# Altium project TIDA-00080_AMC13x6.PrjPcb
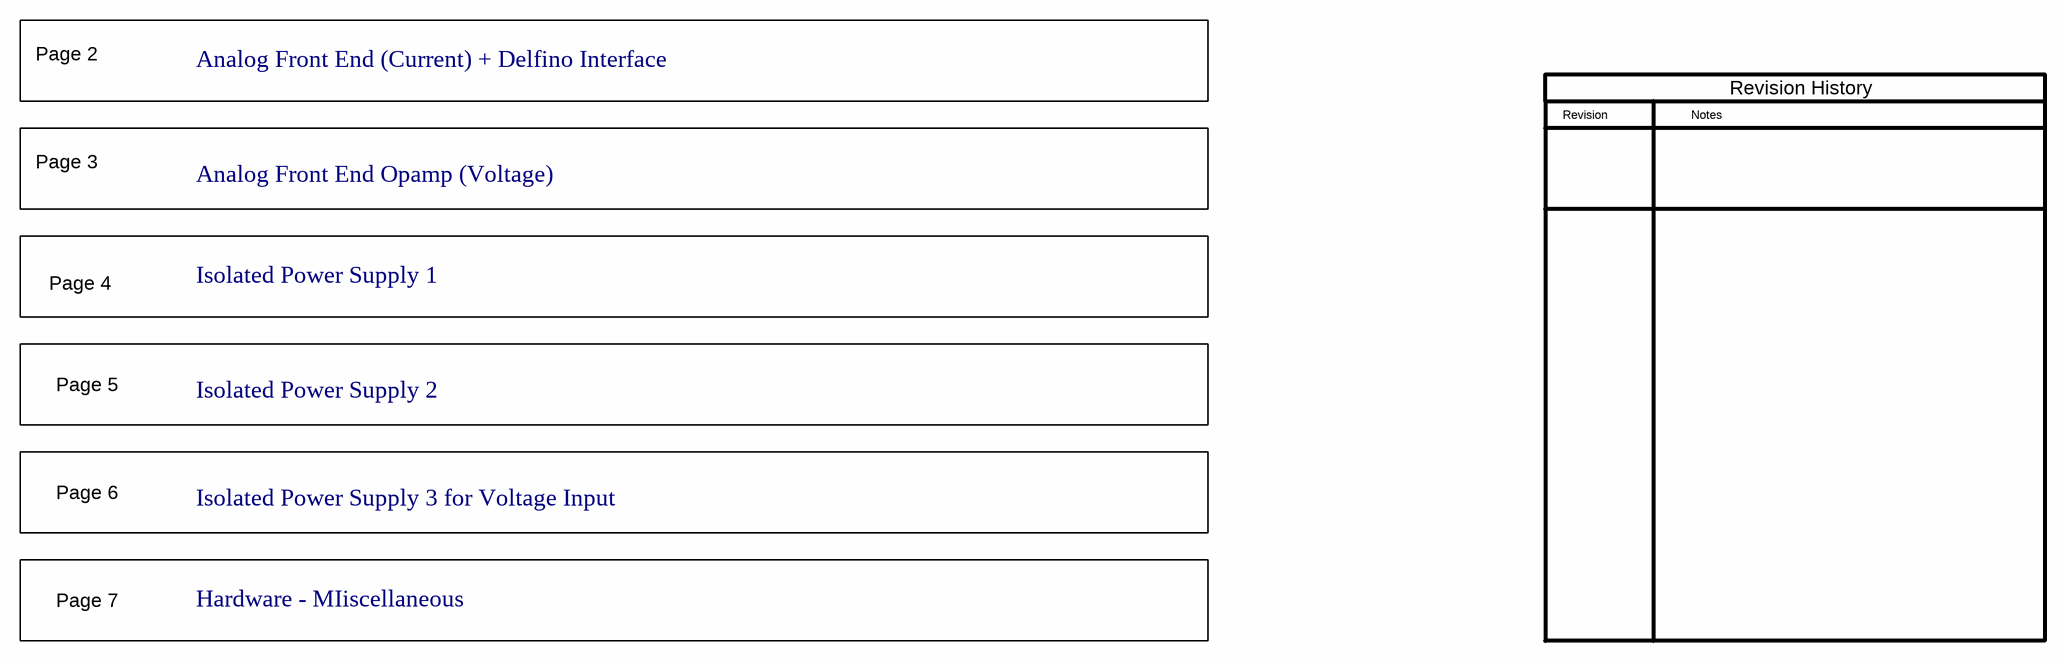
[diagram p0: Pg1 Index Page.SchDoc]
CopyrightYear: 2019; PCB_Layout: Avinash N; PCB_Rev: E1; PRJ_Customer: Public Release; PRJ_Engineer: Sreenivasa; PRJ_Number: TIDA-00080_AMC13x6; PRJ_Title: TIDA-00080_AMC13x6; SCH_Rev: E1; TechSupport: http://www.ti.com/support; TID: 00080
7 sheets, 373 parts. Net scope: flat (ports and power ports of the same name join across sheets).
Board file: TIDA-00080_AMC13x6.PcbDoc
Sheets:
  Pg1 Index Page.SchDoc
  Pg2-Current Sense.SchDoc
  Pg3-Voltage signal condtioning.SchDoc
  Pg4-Power supply 1.SchDoc
  Pg5-Power supply 2.SchDoc
  Pg6-Power supply 3.SchDoc
  Pg7-Hardware.SchDoc

## Sheet Pg1 Index Page.SchDoc: Index Page
size 431 x 279 mm; Date: Not shown in title block; ApprovedBy: Not shown in title block; CheckedBy: Not shown in title block; Author: Not shown in title block; CompanyName: Not shown in title block; Engineer: Not shown in title block; Organization: Not shown in title block; Address1: Not shown in title block; Address2: Not shown in title block; Address3: Not shown in title block; Address4: Not shown in title block; DocumentNumber: 1; Revision: Use project parameter SCH_Rev; SheetNumber: 1; SheetTotal: 7; PageSetup: Record=PageOptions¦CenterHorizontal=True¦CenterVertical=True¦PrintScale=1.00¦XCorrection=1.00¦YCorrection=1.00¦PrintKind=0¦BorderSize=5000000¦LeftOffset=0¦BottomOffset=0¦Orientation=2¦PaperLength=1000¦PaperWidth=1000¦Scale=100¦PaperSource=15¦PrintQuality=600¦MediaType=1¦DitherType=10¦PaperKind=Letter¦PrintScaleMode=1

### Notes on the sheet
- Page 2
- Analog Front End (Current) + Delfino Interface
- Revision
- Notes
- Revision History
- Page 3
- Analog Front End Opamp (Voltage)
- Page 4
- Isolated Power Supply 1
- Page 5
- Isolated Power Supply 2
- Page 6
- Isolated Power Supply 3 for Voltage Input
- Page 7
- Hardware - MIiscellaneous

## Sheet Pg2-Current Sense.SchDoc: Analog Front End (Current) + Delfino Interface
size 431 x 279 mm; Date: Not shown in title block; ApprovedBy: Not shown in title block; CheckedBy: Not shown in title block; Author: Not shown in title block; CompanyName: Not shown in title block; Engineer: Not shown in title block; Organization: Not shown in title block; Address1: Not shown in title block; Address2: Not shown in title block; Address3: Not shown in title block; Address4: Not shown in title block; DocumentNumber: 3; Revision: Use project parameter SCH_Rev; SheetNumber: 2; SheetTotal: 7; PageSetup: Record=PageOptions¦CenterHorizontal=True¦CenterVertical=True¦PrintScale=0.62¦XCorrection=1.00¦YCorrection=1.00¦PrintKind=0¦BorderSize=5000000¦LeftOffset=0¦BottomOffset=0¦Orientation=2¦PaperLength=1000¦PaperWidth=1000¦Scale=100¦PaperSource=15¦PrintQuality=600¦MediaType=1¦DitherType=10¦PaperKind=Letter¦PrintScaleMode=1
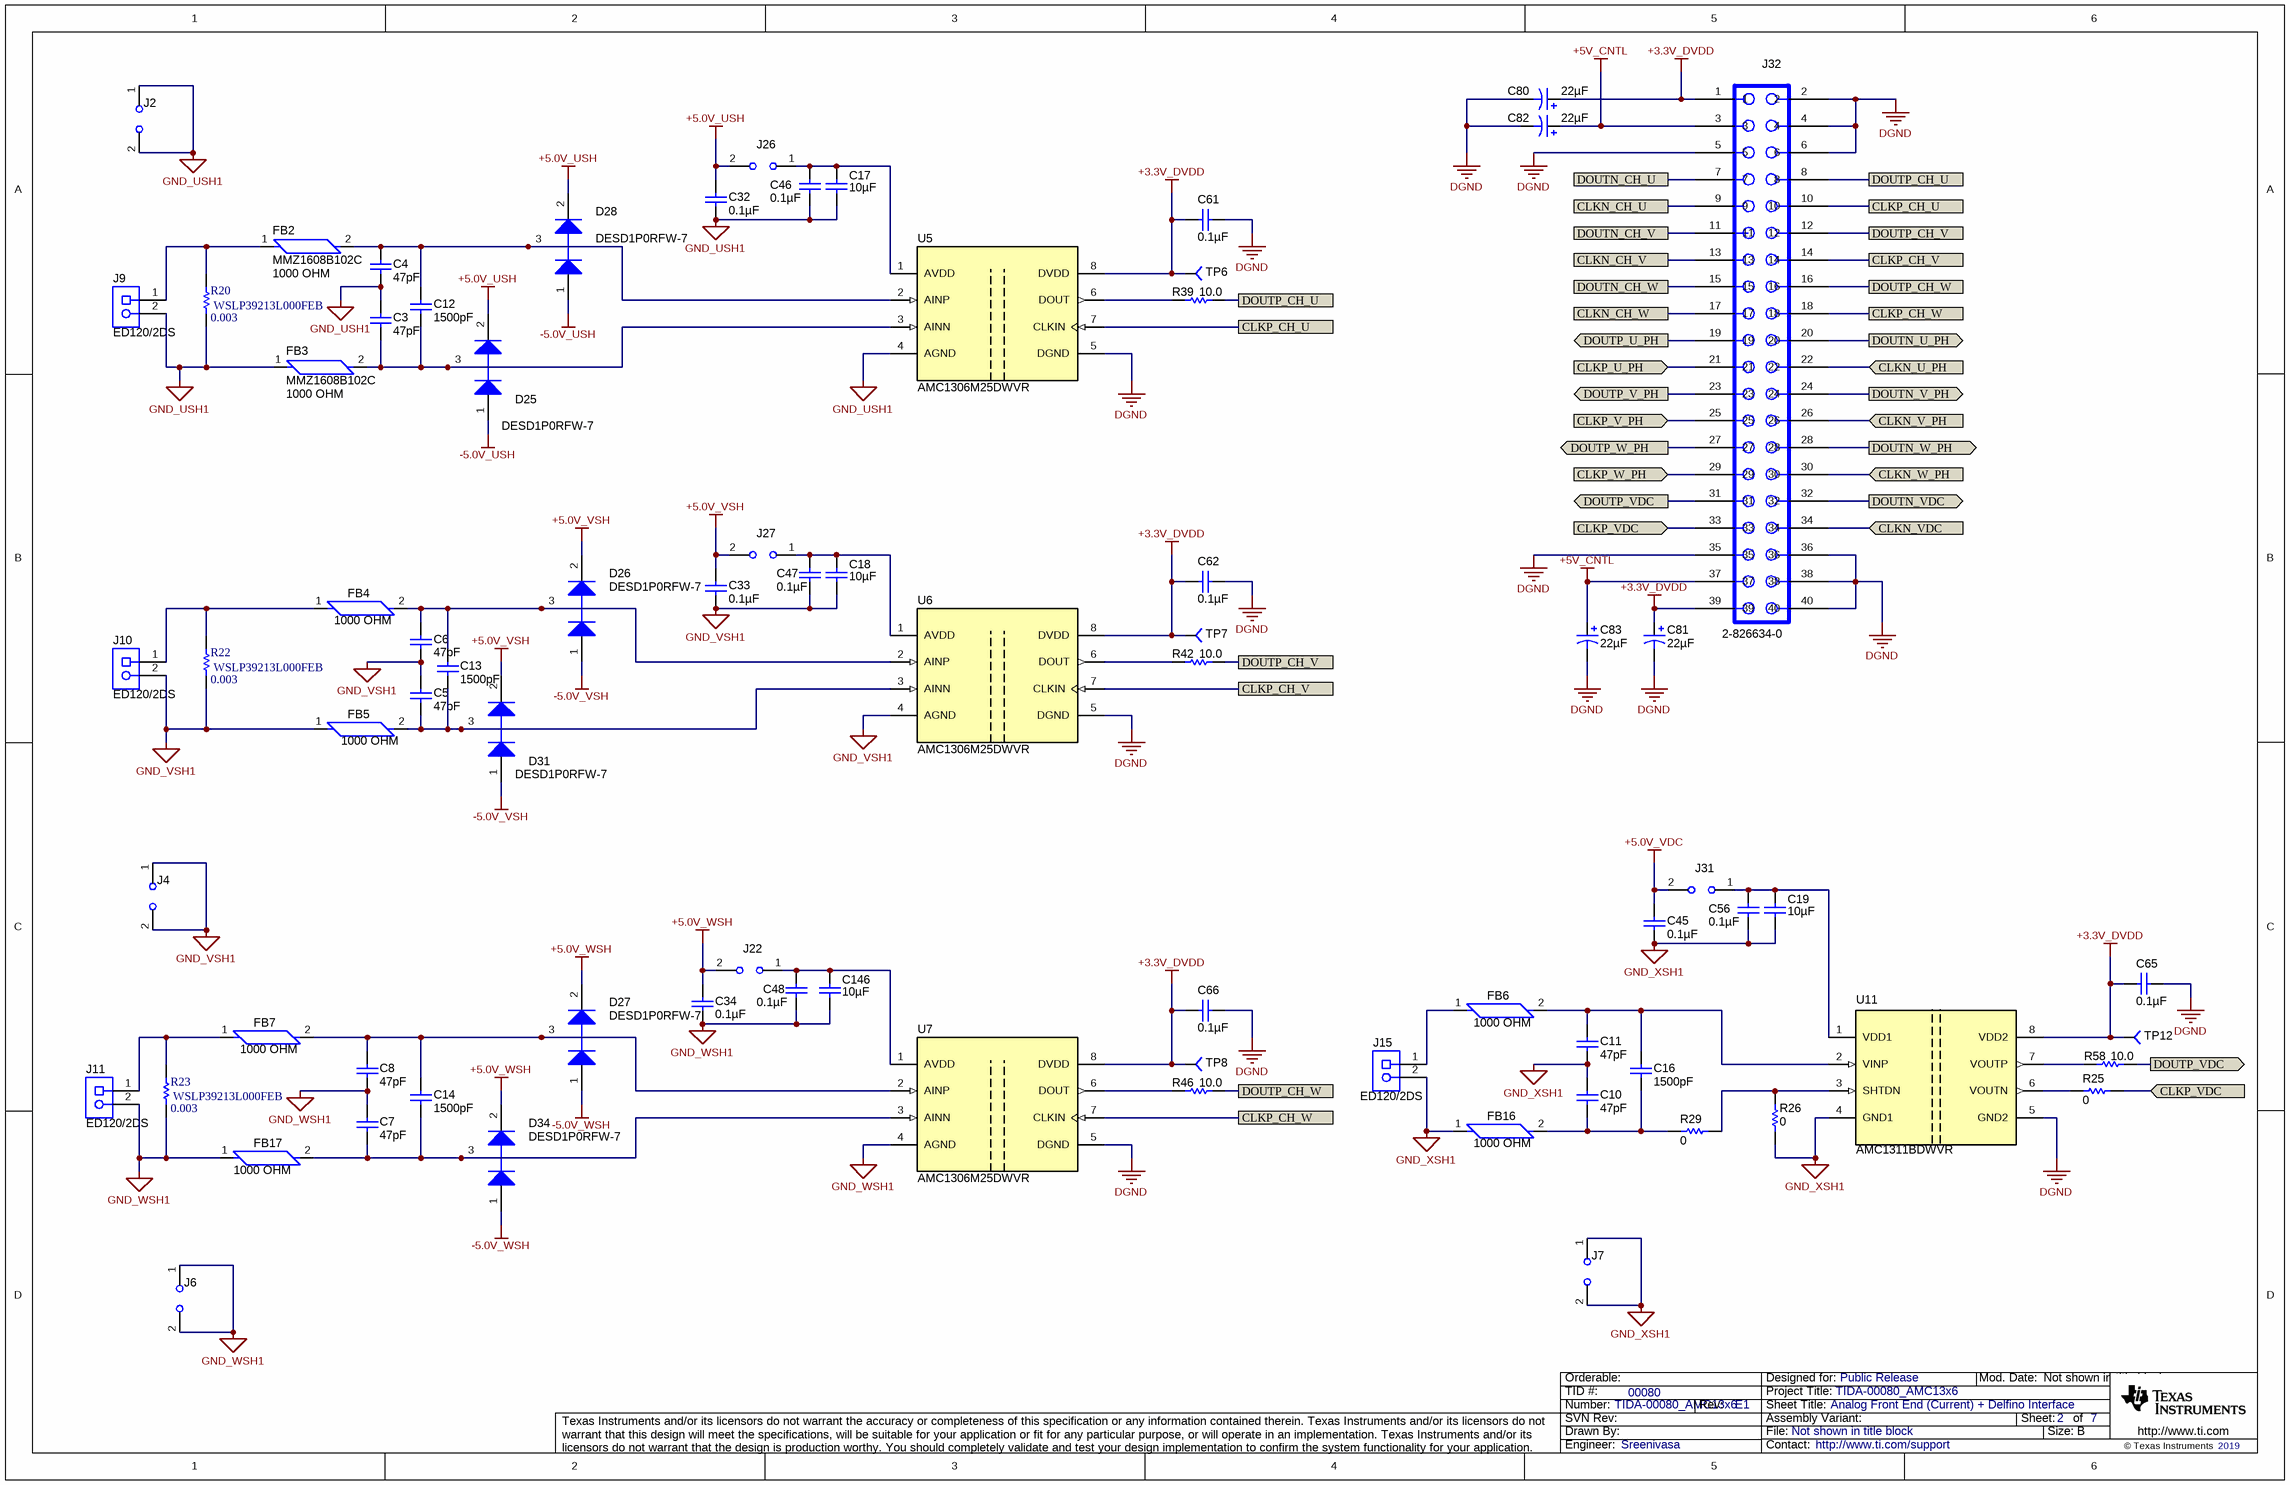
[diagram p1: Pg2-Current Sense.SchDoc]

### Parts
C3  ValueDisplayed: 47pF  [0805_HV]  (hidden comment: GRM21A5C2E470JW01D)
C4  ValueDisplayed: 47pF  [0805_HV]  (hidden comment: GRM21A5C2E470JW01D)
C5  ValueDisplayed: 47pF  [0805_HV]  (hidden comment: GRM21A5C2E470JW01D)
C6  ValueDisplayed: 47pF  [0805_HV]  (hidden comment: GRM21A5C2E470JW01D)
C7  ValueDisplayed: 47pF  [0805_HV]  (hidden comment: GRM21A5C2E470JW01D)
C8  ValueDisplayed: 47pF  [0805_HV]  (hidden comment: GRM21A5C2E470JW01D)
C10  ValueDisplayed: 47pF  [0805_HV]  (hidden comment: GRM21A5C2E470JW01D)
C11  ValueDisplayed: 47pF  [0805_HV]  (hidden comment: GRM21A5C2E470JW01D)
C12  ValueDisplayed: 1500pF  [0603]  (hidden comment: 06031C152KAT2A)
C13  ValueDisplayed: 1500pF  [0603]  (hidden comment: 06031C152KAT2A)
C14  ValueDisplayed: 1500pF  [0603]  (hidden comment: 06031C152KAT2A)
C16  ValueDisplayed: 1500pF  [0603]  (hidden comment: 06031C152KAT2A)
C17  ValueDisplayed: 10µF  [1210]
C18  ValueDisplayed: 10µF  [1210]
C19  ValueDisplayed: 10µF  [1210]
C32  ValueDisplayed: 0.1µF  [0603]
C33  ValueDisplayed: 0.1µF  [0603]
C34  ValueDisplayed: 0.1µF  [0603]
C45  ValueDisplayed: 0.1µF  [0603]
C46  ValueDisplayed: 0.1µF  [0603]
C47  ValueDisplayed: 0.1µF  [0603]
C48  ValueDisplayed: 0.1µF  [0603]
C56  ValueDisplayed: 0.1µF  [0603]
C61  ValueDisplayed: 0.1µF  [0603]
C62  ValueDisplayed: 0.1µF  [0603]
C65  ValueDisplayed: 0.1µF  [0603]
C66  ValueDisplayed: 0.1µF  [0603]
C80  ValueDisplayed: 22µF  [SM_RADIAL_5MM]  (hidden comment: UUD1E220MCL1GS)
C81  ValueDisplayed: 22µF  [SM_RADIAL_5MM]  (hidden comment: UUD1E220MCL1GS)
C82  ValueDisplayed: 22µF  [SM_RADIAL_5MM]  (hidden comment: UUD1E220MCL1GS)
C83  ValueDisplayed: 22µF  [SM_RADIAL_5MM]  (hidden comment: UUD1E220MCL1GS)
C146  ValueDisplayed: 10µF  [1210]
D25  value DESD1P0RFW-7  [SOT-323]
D26  DESD1P0RFW-7  [SOT-323]
D27  DESD1P0RFW-7  [SOT-323]
D28  value DESD1P0RFW-7  [SOT-323]
D31  DESD1P0RFW-7  [SOT-323]
D34  DESD1P0RFW-7  [SOT-323]
FB2  MMZ1608B102C  value 1000 OHM  [FB0603]
FB3  MMZ1608B102C  value 1000 OHM  [FB0603]
FB4  value 1000 OHM  [FB0603]  (hidden comment: MMZ1608B102C)
FB5  value 1000 OHM  [FB0603]  (hidden comment: MMZ1608B102C)
FB6  value 1000 OHM  [FB0603]  (hidden comment: MMZ1608B102C)
FB7  value 1000 OHM  [FB0603]  (hidden comment: MMZ1608B102C)
FB16  value 1000 OHM  [FB0603]  (hidden comment: MMZ1608B102C)
FB17  value 1000 OHM  [FB0603]  (hidden comment: MMZ1608B102C)
J2  (no value)  [HDR100_1X2]
J4  (no value)  [HDR100_1X2]
J6  (no value)  [HDR100_1X2]
J7  (no value)  [HDR100_1X2]
J9  ED120/2DS  [CONN_ED120-2DS]
J10  ED120/2DS  [CONN_ED120-2DS]
J11  ED120/2DS  [CONN_ED120-2DS]
J15  ED120/2DS  [CONN_ED120-2DS]
J22  (no value)  [HDR100_1X2]
J26  (no value)  [HDR100_1X2]
J27  (no value)  [HDR100_1X2]
J31  (no value)  [HDR100_1X2]
J32  2-826634-0  [CONN_61304021021]
R20  WSLP39213L000FEB  value 0.003  [RC3921]
R22  WSLP39213L000FEB  value 0.003  [RC3921]
R23  WSLP39213L000FEB  value 0.003  [RC3921]
R25  ValueDisplayed: 0  [0603]  (hidden comment: CRCW06030000Z0EA)
R26  ValueDisplayed: 0  [0603]  (hidden comment: CRCW06030000Z0EA)
R29  ValueDisplayed: 0  [0603]  (hidden comment: CRCW06030000Z0EA)
R39  value 10.0  [0603]
R42  value 10.0  [0603]
R46  value 10.0  [0603]
R58  value 10.0  [0603]
TP6  (no value)  [TP-040_RND]
TP7  (no value)  [TP-040_RND]
TP8  (no value)  [TP-040_RND]
TP12  (no value)  [TP-040_RND]
U5  AMC1306M25DWVR  [DWV0008A]
U6  AMC1306M25DWVR  [DWV0008A]
U7  AMC1306M25DWVR  [DWV0008A]
U11  AMC1311BDWVR  [DWV0008A]

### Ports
CLKN_CH_U, CLKN_CH_V, CLKN_CH_W, CLKN_U_PH (in), CLKN_V_PH (in), CLKN_VDC (in), CLKN_W_PH (in), CLKP_CH_U, CLKP_CH_V, CLKP_CH_W, CLKP_U_PH (in), CLKP_V_PH (in), CLKP_VDC (in), CLKP_W_PH (in), DOUTN_CH_U, DOUTN_CH_V, DOUTN_CH_W, DOUTN_U_PH (out), DOUTN_V_PH (out), DOUTN_VDC (out), DOUTN_W_PH (out), DOUTP_CH_U, DOUTP_CH_V, DOUTP_CH_W, DOUTP_U_PH (out), DOUTP_V_PH (out), DOUTP_VDC (out), DOUTP_W_PH (out)

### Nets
+3.3V_DVDD: C61.2 C62.2 C65.2 C66.2 C80.1(+) C81.1(+) J32.1 J32.39 TP6.1 TP7.1 TP8.1 TP12.1 U5.8(DVDD) U6.8(DVDD) U7.8(DVDD) U11.8(VDD2)
+5.0V_USH: C32.1 D25.2(K) D28.2(K) J26.2
+5.0V_VDC: C45.1 J31.2
+5.0V_VSH: C33.1 D26.2(K) D31.2(K) J27.2
+5.0V_WSH: C34.1 D27.2(K) D34.2(K) J22.2
+5V_CNTL: C82.1(+) C83.1(+) J32.3 J32.37
-5.0V_USH: D25.1(A) D28.1(A)
-5.0V_VSH: D26.1(A) D31.1(A)
-5.0V_WSH: D27.1(A) D34.1(A)
DGND: C61.1 C62.1 C65.1 C66.1 C80.2(-) C81.2(-) C82.2(-) C83.2(-) J32.2 J32.4 J32.5 J32.6 J32.35 J32.36 J32.38 J32.40 U5.5(DGND) U6.5(DGND) U7.5(DGND) U11.5(GND2)
GND_USH1: C3.1 C4.2 C17.1 C32.2 C46.2 FB3.1 J2.1 J2.2 J9.2 R20.1 U5.4(AGND)
GND_VSH1: C5.1 C6.2 C18.1 C33.2 C47.2 FB5.1 J4.1 J4.2 J10.2 R22.1 U6.4(AGND)
GND_WSH1: C7.1 C8.2 C34.2 C48.2 C146.1 FB17.1 J6.1 J6.2 J11.2 R23.1 U7.4(AGND)
GND_XSH1: C10.1 C11.2 C19.1 C45.2 C56.2 FB16.1 J7.1 J7.2 J15.2 R26.1 U11.4(GND1)
CLKN_CH_U: J32.9 ; port CLKN_CH_U
CLKN_CH_V: J32.13 ; port CLKN_CH_V
CLKN_CH_W: J32.17 ; port CLKN_CH_W
CLKN_U_PH: J32.22 ; port CLKN_U_PH
CLKN_V_PH: J32.26 ; port CLKN_V_PH
CLKN_VDC: J32.34 ; port CLKN_VDC
CLKN_W_PH: J32.30 ; port CLKN_W_PH
CLKP_CH_U: J32.10 U5.7(CLKIN) ; port CLKP_CH_U
CLKP_CH_V: J32.14 U6.7(CLKIN) ; port CLKP_CH_V
CLKP_CH_W: J32.18 U7.7(CLKIN) ; port CLKP_CH_W
CLKP_U_PH: J32.21 ; port CLKP_U_PH
CLKP_V_PH: J32.25 ; port CLKP_V_PH
CLKP_VDC: J32.33 R25.1 ; port CLKP_VDC
CLKP_W_PH: J32.29 ; port CLKP_W_PH
DOUTN_CH_U: J32.7 ; port DOUTN_CH_U
DOUTN_CH_V: J32.11 ; port DOUTN_CH_V
DOUTN_CH_W: J32.15 ; port DOUTN_CH_W
DOUTN_U_PH: J32.20 ; port DOUTN_U_PH
DOUTN_V_PH: J32.24 ; port DOUTN_V_PH
DOUTN_VDC: J32.32 ; port DOUTN_VDC
DOUTN_W_PH: J32.28 ; port DOUTN_W_PH
DOUTP_CH_U: J32.8 R39.2 ; port DOUTP_CH_U
DOUTP_CH_V: J32.12 R42.2 ; port DOUTP_CH_V
DOUTP_CH_W: J32.16 R46.2 ; port DOUTP_CH_W
DOUTP_U_PH: J32.19 ; port DOUTP_U_PH
DOUTP_V_PH: J32.23 ; port DOUTP_V_PH
DOUTP_VDC: J32.31 R58.2 ; port DOUTP_VDC
DOUTP_W_PH: J32.27 ; port DOUTP_W_PH
NetC3_2: C3.2 C12.2 D25.3(C) FB3.2 U5.3(AINN)
NetC4_1: C4.1 C12.1 D28.3(C) FB2.2 U5.2(AINP)
NetC5_2: C5.2 C13.2 D31.3(C) FB5.2 U6.3(AINN)
NetC6_1: C6.1 C13.1 D26.3(C) FB4.2 U6.2(AINP)
NetC7_2: C7.2 C14.2 D34.3(C) FB17.2 U7.3(AINN)
NetC8_1: C8.1 C14.1 D27.3(C) FB7.2 U7.2(AINP)
NetC10_2: C10.2 C16.2 FB16.2 R29.2
NetC11_1: C11.1 C16.1 FB6.2 U11.2(VINP)
NetC17_2: C17.2 C46.1 J26.1 U5.1(AVDD)
NetC18_2: C18.2 C47.1 J27.1 U6.1(AVDD)
NetC19_2: C19.2 C56.1 J31.1 U11.1(VDD1)
NetC48_1: C48.1 C146.2 J22.1 U7.1(AVDD)
NetFB2_1: FB2.1 J9.1 R20.2
NetFB4_1: FB4.1 J10.1 R22.2
NetFB6_1: FB6.1 J15.1
NetFB7_1: FB7.1 J11.1 R23.2
NetR25_2: R25.2 U11.6(VOUTN)
NetR26_2: R26.2 R29.1 U11.3(SHTDN)
NetR39_1: R39.1 U5.6(DOUT)
NetR42_1: R42.1 U6.6(DOUT)
NetR46_1: R46.1 U7.6(DOUT)
NetR58_1: R58.1 U11.7(VOUTP)

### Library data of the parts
C3-C8 C10 C11 = GRM21A5C2E470JW01D: CAP, CERM, 47pF, 500V, +/-5%, C0G/NP0, 0805; Manufacturer: MuRata; Polarized: N; CompType: Capacitor; U/M: EA; Cap_F: 0.000000000047; Tolerance_%: 5; Value1: Unknown; VDC_V: 250; Value2: 250V; TaMin_C: -55; TaMax_C: 125; Cap_Case: 0805
C12-C14 C16 = 06031C152KAT2A: CAP, CERM, 1500pF, 100V, +/-10%, X7R, 0603; Manufacturer: AVX; Polarized: N; CompType: Capacitor; U/M: EA; Cap_F: 0.0000000015; Tolerance_%: 10; ESR_Ohm: 0.229; Value1: 0.229 ohm; VDC_V: 100; TaMin_C: -55; TaMax_C: 125
C17-C19 C146 = GMK325AB7106MM-T: CAP, CERM, 10uF, 35V, +/-20%, X7R, 1210; Manufacturer: Taiyo Yuden; Polarized: N; CompType: Capacitor; U/M: EA; Cap_F: 0.00001; Tolerance_%: 20; Value1: Unknown; VDC_V: 35; TaMin_C: -55; TaMax_C: 125
C32-C34 C45-C48 C56 = C0603C104K5RACTU: CAP, CERM, 0.1uF, 50V, +/-10%, X7R, 0603; Manufacturer: Kemet; Polarized: N; CompType: Capacitor; U/M: EA; Cap_F: 0.0000001; Tolerance_%: 10; Value1: Unknown; VDC_V: 50; TaMin_C: -55; TaMax_C: 125
C61 C62 C65 C66 = 06033C104JAT2A: CAP, CERM, 0.1uF, 25V, +/-5%, X7R, 0603; Manufacturer: AVX; Polarized: N; CompType: Capacitor; U/M: EA; Cap_F: 0.0000001; Tolerance_%: 5; ESR_Ohm: 0.05; Value1: 0.05 ohm; VDC_V: 25; TaMin_C: -55; TaMax_C: 125
C80-C83 = UUD1E220MCL1GS: CAP, AL, 22uF, 25V, +/-20%, 0.76 ohm, SMD; Manufacturer: Nichicon; Polarized: Y; CompType: Capacitor; U/M: EA; Cap_F: 0.000022; Tolerance_%: 20; VDC_V: 25; ESR_Ohm: 0.76; IRMS_A: 0.15; TaMin_C: -55; TaMax_C: 105; Cap_Case: 5x5.8
D25 D28 = BAV99WT1G: Diode, P-N, 70V, 0.2A, SOT-323; Manufacturer: Diodes Inc
D26 D27 D31 D34 = BAV99WT1G: Diode, P-N, 70V, 0.2A, SOT-323; Manufacturer: Diodes Inc; Value: DNP
FB2-FB7 FB16 FB17 = MMZ1608B102C: FERRITE CHIP 1000 OHM 300MA 0603; Manufacturer: TDK Corporation; CompType: Ferrite Bead
J2 J4 J6 J7 J22 J26 J27 J31 = JUMPER_2X100MIL: Header, Male 2-pin, 100mil spacing,; Manufacturer: FCI; PartNumber: 68001-402HLF; area: 20000; Value: 68001-402HLF
J9-J11 J15 = ED120/2DS: TERMINAL BLOCK 5.08MM VERT 2POS, TH; Manufacturer: On-Shore Technology; SymbolCreator: a0412235; U/M: EA
J32 = CONN_61304021021: Connector, Right Angle 2x20 pin, 100mil spacing; Manufacturer: TE Connectivity; area: 1.262.250
R20 R22 R23 = WSLP39213L000FEB: RESISTOR, SMD, 0.003 OHM, 1%, 5W, 3921; Manufacturer: VISHAY DALE; SymbolCreator: x0199378
R25 R26 R29 = CRCW06030000Z0EA: RES, 0, 5%, 0.1 W, 0603; Manufacturer: Vishay-Dale; CompType: Resistor; Value: 0; Value_Code: 0000; Tolerance_%: 5; Power_W: 0.1; Value2: 0.1W; VDC_V: 75; TempCo: 200 ppm/C; SizeArea_mm2: 1.28; SizeX_mm: 1.6; SizeY_mm: 0.8; SizeZ_mm: 1; EIA_Code: E24; U/M: EA; AEC Category: Q200; Green_Lifecycle: Active; Green_REACh: Passed
R39 R42 R46 R58 = CRCW060310R0FKEA: RES, 10.0 ohm, 1%, 0.1W, 0603; Manufacturer: Vishay-Dale; CompType: Resistor; Res_ohm: 10; Value_Code: 10R0; Tolerance_%: 1; Power_W: 0.1; VDC_V: 75; TempCo: 100 ppm/C; EIA_Code: E96; U/M: EA
TP6-TP8 TP12 = TP-040_RND: Test Point, O.040 Hole; Manufacturer: STD; Value: STD
U5-U7 = AMC1306M25DWVR: Small Reinforced Isolated Modulator With +/-250mV Input and CMOS Interface, DWV0008A (SOIC-8); Manufacturer: Texas Instruments; SymbolCreator: Altium; SizeArea_mm2: 67.275; SizeAreaWB_mm2: 105.975; SizeX_mm: 11.5; SizeY_mm: 5.85; SizeZ_mm: 2.8; CompType: IC; U/M: EA
U11 = AMC1311DWVR: Precision, 2-V Input, Reinforced Isolated Amplifier, DWV0008A (SOIC-8); Manufacturer: Texas Instruments; SymbolCreator: a0411947; SizeArea_mm2: 67.275; SizeAreaWB_mm2: 105.975; SizeX_mm: 11.5; SizeY_mm: 5.85; SizeZ_mm: 2.8; CompType: IC; U/M: EA

## Sheet Pg3-Voltage signal condtioning.SchDoc: Analog Front End Opamp (Voltage)
size 431 x 279 mm; Date: Not shown in title block; ApprovedBy: Not shown in title block; CheckedBy: Not shown in title block; Author: Not shown in title block; CompanyName: Not shown in title block; Engineer: Not shown in title block; Organization: Not shown in title block; Address1: Not shown in title block; Address2: Not shown in title block; Address3: Not shown in title block; Address4: Not shown in title block; DocumentNumber: 4; Revision: Use project parameter SCH_Rev; SheetNumber: 3; SheetTotal: 7; PageSetup: Record=PageOptions¦CenterHorizontal=True¦CenterVertical=True¦PrintScale=1.00¦XCorrection=1.00¦YCorrection=1.00¦PrintKind=0¦BorderSize=5000000¦LeftOffset=0¦BottomOffset=0¦Orientation=2¦PaperLength=1000¦PaperWidth=1000¦Scale=100¦PaperSource=15¦PrintQuality=600¦MediaType=1¦DitherType=10¦PaperKind=Letter¦PrintScaleMode=1
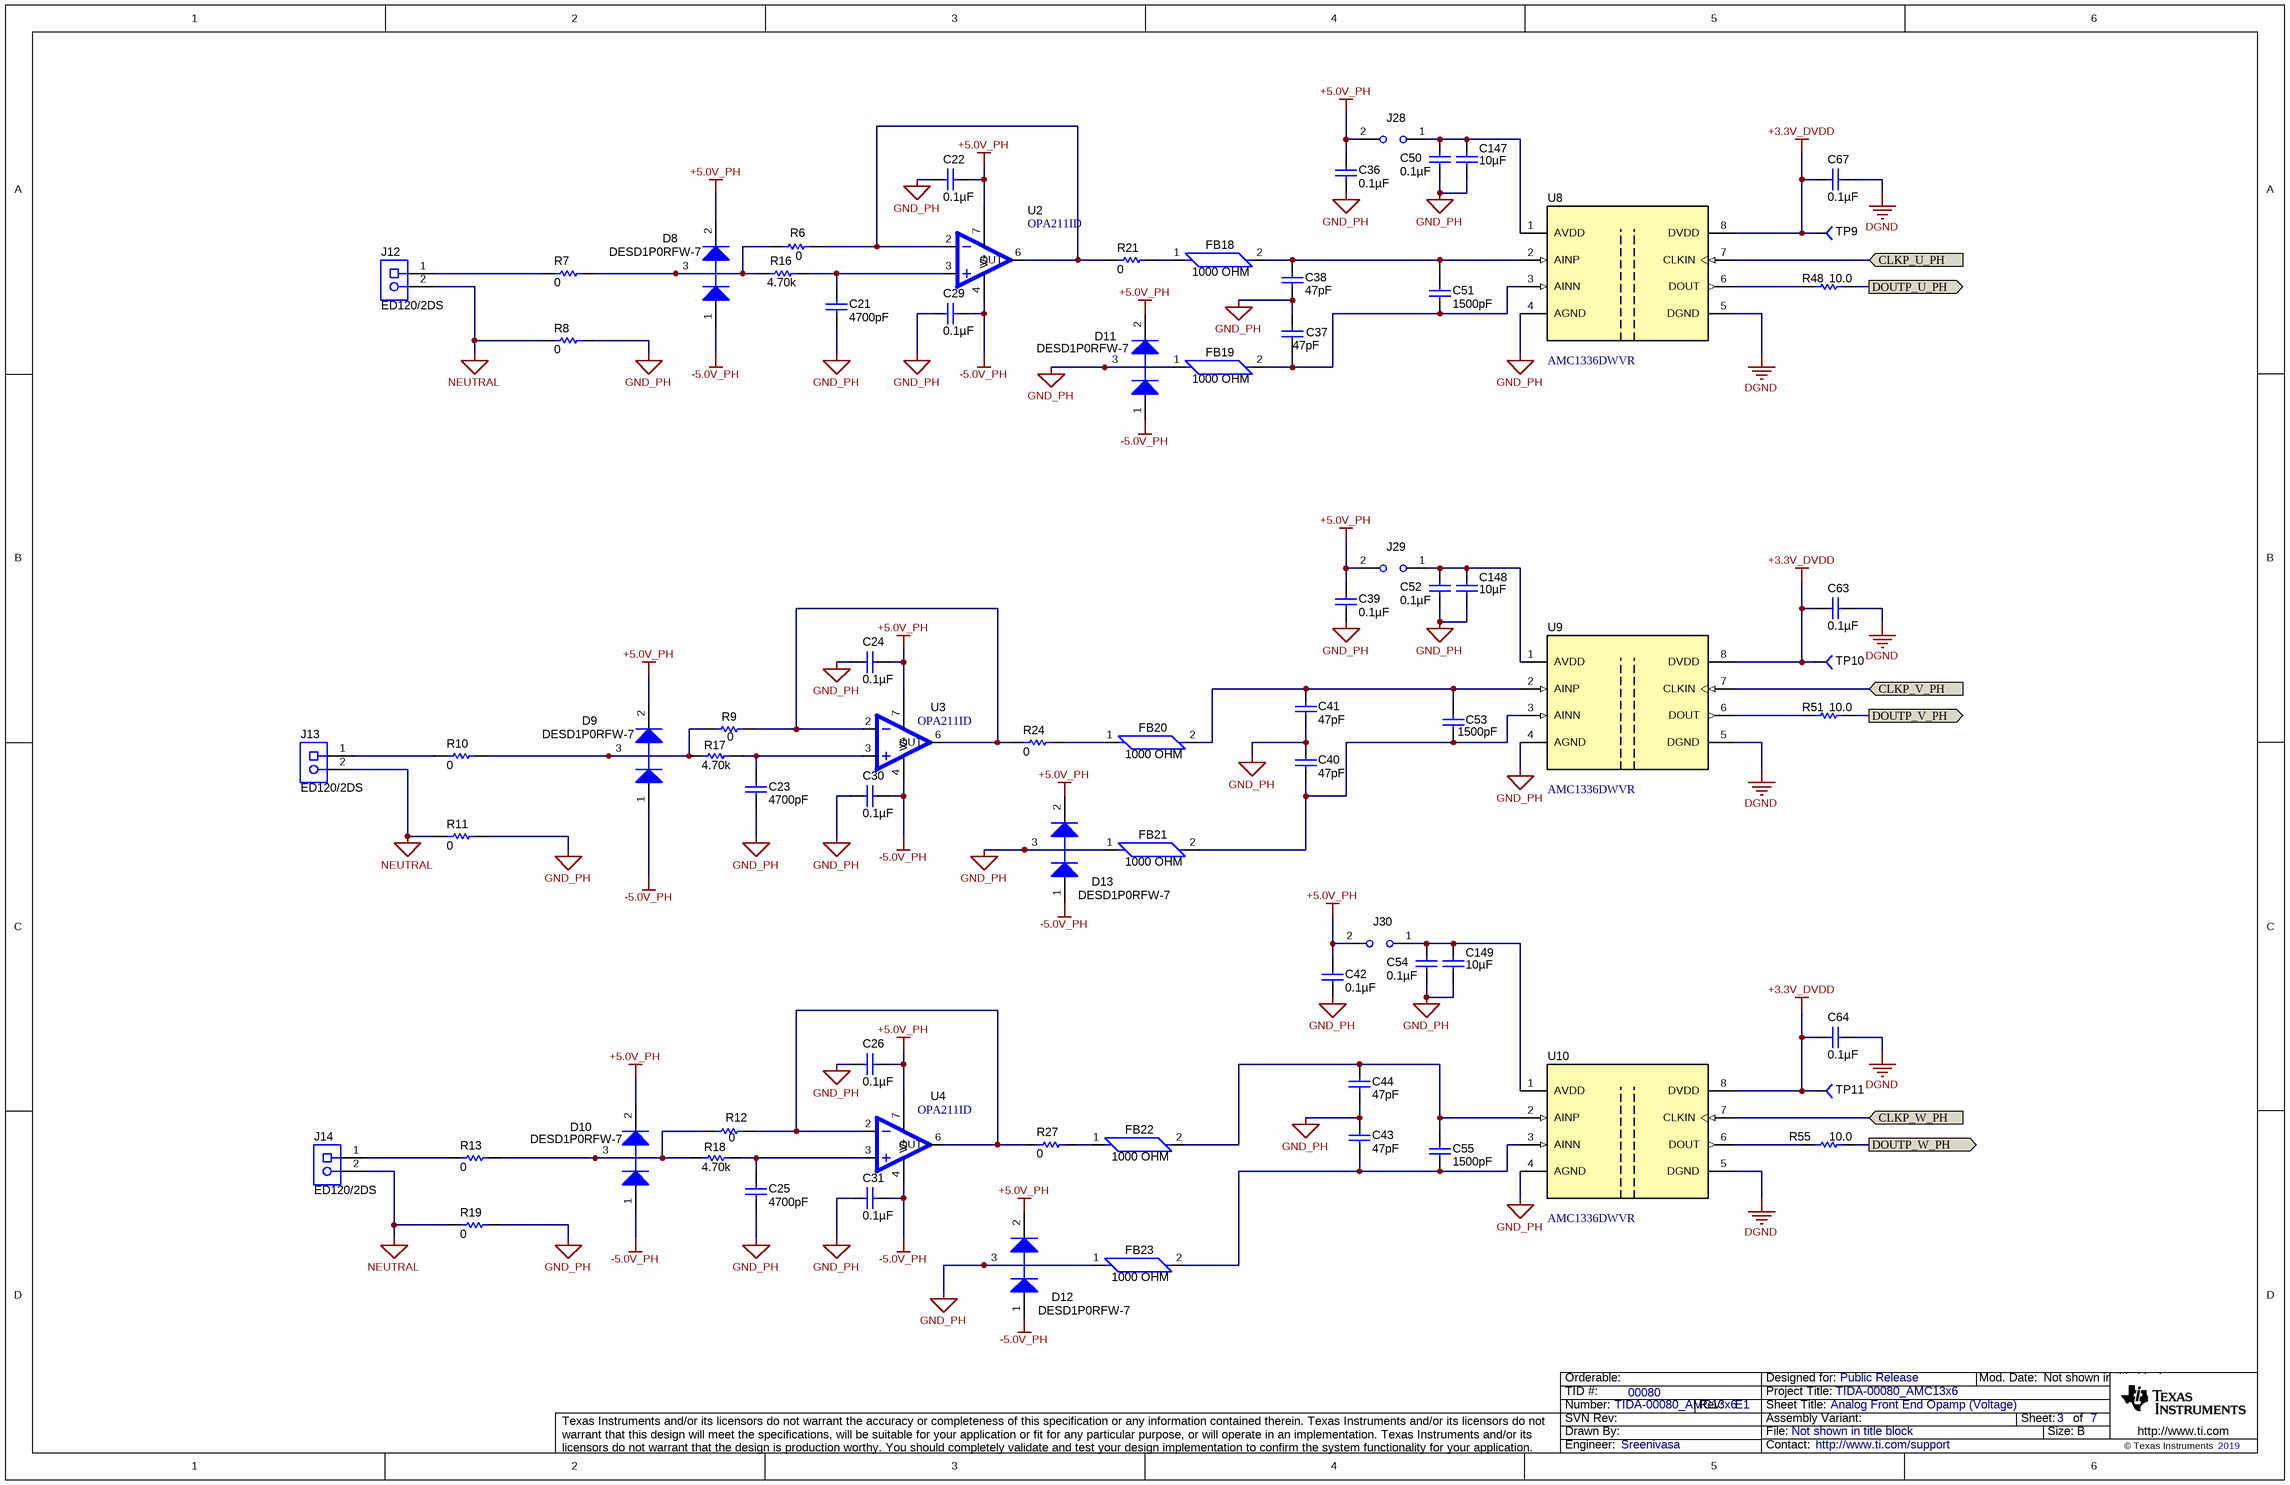
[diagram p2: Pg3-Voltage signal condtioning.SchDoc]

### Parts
C21  ValueDisplayed: 4700pF  [0603]
C22  ValueDisplayed: 0.1µF  [0603]
C23  ValueDisplayed: 4700pF  [0603]
C24  ValueDisplayed: 0.1µF  [0603]
C25  ValueDisplayed: 4700pF  [0603]
C26  ValueDisplayed: 0.1µF  [0603]
C29  ValueDisplayed: 0.1µF  [0603]
C30  ValueDisplayed: 0.1µF  [0603]
C31  ValueDisplayed: 0.1µF  [0603]
C36  ValueDisplayed: 0.1µF  [0603]
C37  ValueDisplayed: 47pF  [0805_HV]  (hidden comment: GRM21A5C2E470JW01D)
C38  ValueDisplayed: 47pF  [0805_HV]  (hidden comment: GRM21A5C2E470JW01D)
C39  ValueDisplayed: 0.1µF  [0603]
C40  ValueDisplayed: 47pF  [0805_HV]  (hidden comment: GRM21A5C2E470JW01D)
C41  ValueDisplayed: 47pF  [0805_HV]  (hidden comment: GRM21A5C2E470JW01D)
C42  ValueDisplayed: 0.1µF  [0603]
C43  ValueDisplayed: 47pF  [0805_HV]  (hidden comment: GRM21A5C2E470JW01D)
C44  ValueDisplayed: 47pF  [0805_HV]  (hidden comment: GRM21A5C2E470JW01D)
C50  ValueDisplayed: 0.1µF  [0603]
C51  ValueDisplayed: 1500pF  [0603]  (hidden comment: 06031C152KAT2A)
C52  ValueDisplayed: 0.1µF  [0603]
C53  ValueDisplayed: 1500pF  [0603]  (hidden comment: 06031C152KAT2A)
C54  ValueDisplayed: 0.1µF  [0603]
C55  ValueDisplayed: 1500pF  [0603]  (hidden comment: 06031C152KAT2A)
C63  ValueDisplayed: 0.1µF  [0603]
C64  ValueDisplayed: 0.1µF  [0603]
C67  ValueDisplayed: 0.1µF  [0603]
C147  ValueDisplayed: 10µF  [1210]
C148  ValueDisplayed: 10µF  [1210]
C149  ValueDisplayed: 10µF  [1210]
D8  DESD1P0RFW-7  [SOT-323]
D9  DESD1P0RFW-7  [SOT-323]
D10  DESD1P0RFW-7  [SOT-323]
D11  value DESD1P0RFW-7  [SOT-323]
D12  value DESD1P0RFW-7  [SOT-323]
D13  value DESD1P0RFW-7  [SOT-323]
FB18  value 1000 OHM  [FB0603]  (hidden comment: MMZ1608B102C)
FB19  value 1000 OHM  [FB0603]  (hidden comment: MMZ1608B102C)
FB20  value 1000 OHM  [FB0603]  (hidden comment: MMZ1608B102C)
FB21  value 1000 OHM  [FB0603]  (hidden comment: MMZ1608B102C)
FB22  value 1000 OHM  [FB0603]  (hidden comment: MMZ1608B102C)
FB23  value 1000 OHM  [FB0603]  (hidden comment: MMZ1608B102C)
J12  ED120/2DS  [CONN_ED120-2DS]
J13  ED120/2DS  [CONN_ED120-2DS]
J14  ED120/2DS  [CONN_ED120-2DS]
J28  (no value)  [HDR100_1X2]
J29  (no value)  [HDR100_1X2]
J30  (no value)  [HDR100_1X2]
R6  value 0  [0603]  (hidden comment: CRCW06030000Z0EA)
R7  value 0  [0805_HV]  (hidden comment: CRCW08050000Z0EA)
R8  value 0  [0805_HV]  (hidden comment: CRCW08050000Z0EA)
R9  value 0  [0603]  (hidden comment: CRCW06030000Z0EA)
R10  value 0  [0805_HV]  (hidden comment: CRCW08050000Z0EA)
R11  value 0  [0805_HV]  (hidden comment: CRCW08050000Z0EA)
R12  value 0  [0603]  (hidden comment: CRCW06030000Z0EA)
R13  value 0  [0805_HV]  (hidden comment: CRCW08050000Z0EA)
R16  value 4.70k  [0603]
R17  value 4.70k  [0603]
R18  value 4.70k  [0603]
R19  value 0  [0805_HV]  (hidden comment: CRCW08050000Z0EA)
R21  value 0  [0603]
R24  value 0  [0603]
R27  value 0  [0603]
R48  value 10.0  [0603]
R51  value 10.0  [0603]
R55  value 10.0  [0603]
TP9  (no value)  [TP-040_RND]
TP10  (no value)  [TP-040_RND]
TP11  (no value)  [TP-040_RND]
U2  OPA211ID  [SO8]
U3  OPA211ID  [SO8]
U4  OPA211ID  [SO8]
U8  AMC1336DWVR  [DWV0008A]
U9  AMC1336DWVR  [DWV0008A]
U10  AMC1336DWVR  [DWV0008A]

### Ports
CLKP_U_PH (in), CLKP_V_PH (in), CLKP_W_PH (in), DOUTP_U_PH (out), DOUTP_V_PH (out), DOUTP_W_PH (out)

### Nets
+3.3V_DVDD: C63.2 C64.2 C67.2 TP9.1 TP10.1 TP11.1 U8.8(DVDD) U9.8(DVDD) U10.8(DVDD)
+5.0V_PH: C22.2 C24.2 C26.2 C36.1 C39.1 C42.1 D8.2(K) D9.2(K) D10.2(K) D11.2(K) D12.2(K) D13.2(K) J28.2 J29.2 J30.2 U2.7(V+) U3.7(V+) U4.7(V+)
-5.0V_PH: C29.2 C30.2 C31.2 D8.1(A) D9.1(A) D10.1(A) D11.1(A) D12.1(A) D13.1(A) U2.4(V-) U3.4(V-) U4.4(V-)
DGND: C63.1 C64.1 C67.1 U8.5(DGND) U9.5(DGND) U10.5(DGND)
GND_PH: C21.2 C22.1 C23.2 C24.1 C25.2 C26.1 C29.1 C30.1 C31.1 C36.2 C37.1 C38.1 C39.2 C40.1 C41.1 C42.2 C43.1 C44.1 C50.2 C52.2 C54.2 C147.1 C148.1 C149.1 D11.3(C) D12.3(C) D13.3(C) FB19.1 FB21.1 FB23.1 R8.2 R11.2 R19.2 U8.4(AGND) U9.4(AGND) U10.4(AGND)
NEUTRAL: J12.2 J13.2 J14.2 R8.1 R11.1 R19.1
CLKP_U_PH: U8.7(CLKIN) ; port CLKP_U_PH
CLKP_V_PH: U9.7(CLKIN) ; port CLKP_V_PH
CLKP_W_PH: U10.7(CLKIN) ; port CLKP_W_PH
DOUTP_U_PH: R48.2 ; port DOUTP_U_PH
DOUTP_V_PH: R51.2 ; port DOUTP_V_PH
DOUTP_W_PH: R55.2 ; port DOUTP_W_PH
NetC21_1: C21.1 R16.2 U2.3
NetC23_1: C23.1 R17.2 U3.3
NetC25_1: C25.1 R18.2 U4.3
NetC37_2: C37.2 C51.2 FB19.2 U8.3(AINN)
NetC38_2: C38.2 C51.1 FB18.2 U8.2(AINP)
NetC40_2: C40.2 C53.2 FB21.2 U9.3(AINN)
NetC41_2: C41.2 C53.1 FB20.2 U9.2(AINP)
NetC43_2: C43.2 C55.2 FB23.2 U10.3(AINN)
NetC44_2: C44.2 C55.1 FB22.2 U10.2(AINP)
NetC50_1: C50.1 C147.2 J28.1 U8.1(AVDD)
NetC52_1: C52.1 C148.2 J29.1 U9.1(AVDD)
NetC54_1: C54.1 C149.2 J30.1 U10.1(AVDD)
NetD8_3: D8.3(C) R6.1 R7.2 R16.1
NetD9_3: D9.3(C) R9.1 R10.2 R17.1
NetD10_3: D10.3(C) R12.1 R13.2 R18.1
NetFB18_1: FB18.1 R21.2
NetFB20_1: FB20.1 R24.2
NetFB22_1: FB22.1 R27.2
NetJ12_1: J12.1 R7.1
NetJ13_1: J13.1 R10.1
NetJ14_1: J14.1 R13.1
NetR6_2: R6.2 R21.1 U2.2 U2.6(OUT)
NetR9_2: R9.2 R24.1 U3.2 U3.6(OUT)
NetR12_2: R12.2 R27.1 U4.2 U4.6(OUT)
NetR48_1: R48.1 U8.6(DOUT)
NetR51_1: R51.1 U9.6(DOUT)
NetR55_1: R55.1 U10.6(DOUT)

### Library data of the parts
C21 C23 C25 = 06031C472KAT2A: CAP, CERM, 4700pF, 100V, +/-10%, X7R, 0603; Manufacturer: AVX; Polarized: N; CompType: Capacitor; U/M: EA; Cap_F: 0.0000000047; Tolerance_%: 10; ESR_Ohm: 0.136; Value1: 0.136 ohm; VDC_V: 100; TaMin_C: -55; TaMax_C: 125
C22 C24 C26 C29-C31 C36 C39 C42 C50 C52 C54 = C0603C104K5RACTU: as C32 on sheet Pg2-Current Sense
C37 C38 C40 C41 C43 C44 = GRM21A5C2E470JW01D: as C3 on sheet Pg2-Current Sense
C51 C53 C55 = 06031C152KAT2A: as C12 on sheet Pg2-Current Sense
C63 C64 C67 = 06033C104JAT2A: as C61 on sheet Pg2-Current Sense
C147-C149 = GMK325AB7106MM-T: as C17 on sheet Pg2-Current Sense
D8-D10 = BAV99WT1G: as D26 on sheet Pg2-Current Sense
D11-D13 = BAV99WT1G: as D25 on sheet Pg2-Current Sense
FB18-FB23 = MMZ1608B102C: as FB2 on sheet Pg2-Current Sense
J12-J14 = ED120/2DS: as J9 on sheet Pg2-Current Sense
J28-J30 = JUMPER_2X100MIL: as J2 on sheet Pg2-Current Sense
R6 R9 R12 R21 R24 R27 = CRCW06030000Z0EA: RES, 0 ohm, 5%, 0.1W, 0603; Manufacturer: Vishay-Dale; CompType: Resistor; Value_Code: 0000; Tolerance_%: 5; Power_W: 0.1; VDC_V: 75; TempCo: 200 ppm/C; EIA_Code: E24; U/M: EA
R7 R8 R10 R11 R13 R19 = CRCW08050000Z0EA: RES, 0 ohm, 5%, 0.125W, 0805; Manufacturer: Vishay-Dale; CompType: Resistor; Value_Code: 0000; Tolerance_%: 5; Power_W: 0.125; VDC_V: 150; TempCo: 200 ppm/C; EIA_Code: E24; U/M: EA
R16-R18 = RC0603FR-074K7L: RES, 4.70k ohm, 1%, 0.1W, 0603; Manufacturer: Yageo America; CompType: Resistor; Res_ohm: 4700; Value_Code: 4k70; Tolerance_%: 1; Power_W: 0.1; VDC_V: 150; TempCo: 200 ppm/C; U/M: EA
R48 R51 R55 = CRCW060310R0FKEA: as R39 on sheet Pg2-Current Sense
TP9-TP11 = TP-040_RND: as TP6 on sheet Pg2-Current Sense
U2-U4 = OPA211AID: IC, 1.1nV/vHz Noise, Low Power, Precision OpAmp; Manufacturer: Texas Instruments; Alternate Manufacturer: None; Area: 75900
U8-U10 = CMP-0860008-1: AMC1336 Small, High-Precision, Reinforced Isolated Delta-Sigma Modulator With Input Optimized for Voltage Sensing Applications, DWV0008A (SOIC-8); Manufacturer: Texas Instruments; AEC Qualified: N; AEC Category: Q200; SizeY_mm: 5.85; SizeX_mm: 11.5; SizeAreaWB_mm2: 105.975; SizeArea_mm2: 67.275; CompType: IC; SizeZ_mm: 2.8

## Sheet Pg4-Power supply 1.SchDoc: Isolated Poser Supply 1
size 431 x 279 mm; Date: Not shown in title block; ApprovedBy: Not shown in title block; CheckedBy: Not shown in title block; Author: Not shown in title block; CompanyName: Not shown in title block; Engineer: Not shown in title block; Organization: Not shown in title block; Address1: Not shown in title block; Address2: Not shown in title block; Address3: Not shown in title block; Address4: Not shown in title block; DocumentNumber: 5; Revision: Use project parameter SCH_Rev; SheetNumber: 4; SheetTotal: 7; PageSetup: Record=PageOptions¦CenterHorizontal=True¦CenterVertical=True¦PrintScale=0.62¦XCorrection=1.00¦YCorrection=1.00¦PrintKind=0¦BorderSize=5000000¦LeftOffset=0¦BottomOffset=0¦Orientation=2¦PaperLength=1000¦PaperWidth=1000¦Scale=100¦PaperSource=15¦PrintQuality=600¦MediaType=1¦DitherType=10¦PaperKind=Letter¦PrintScaleMode=1
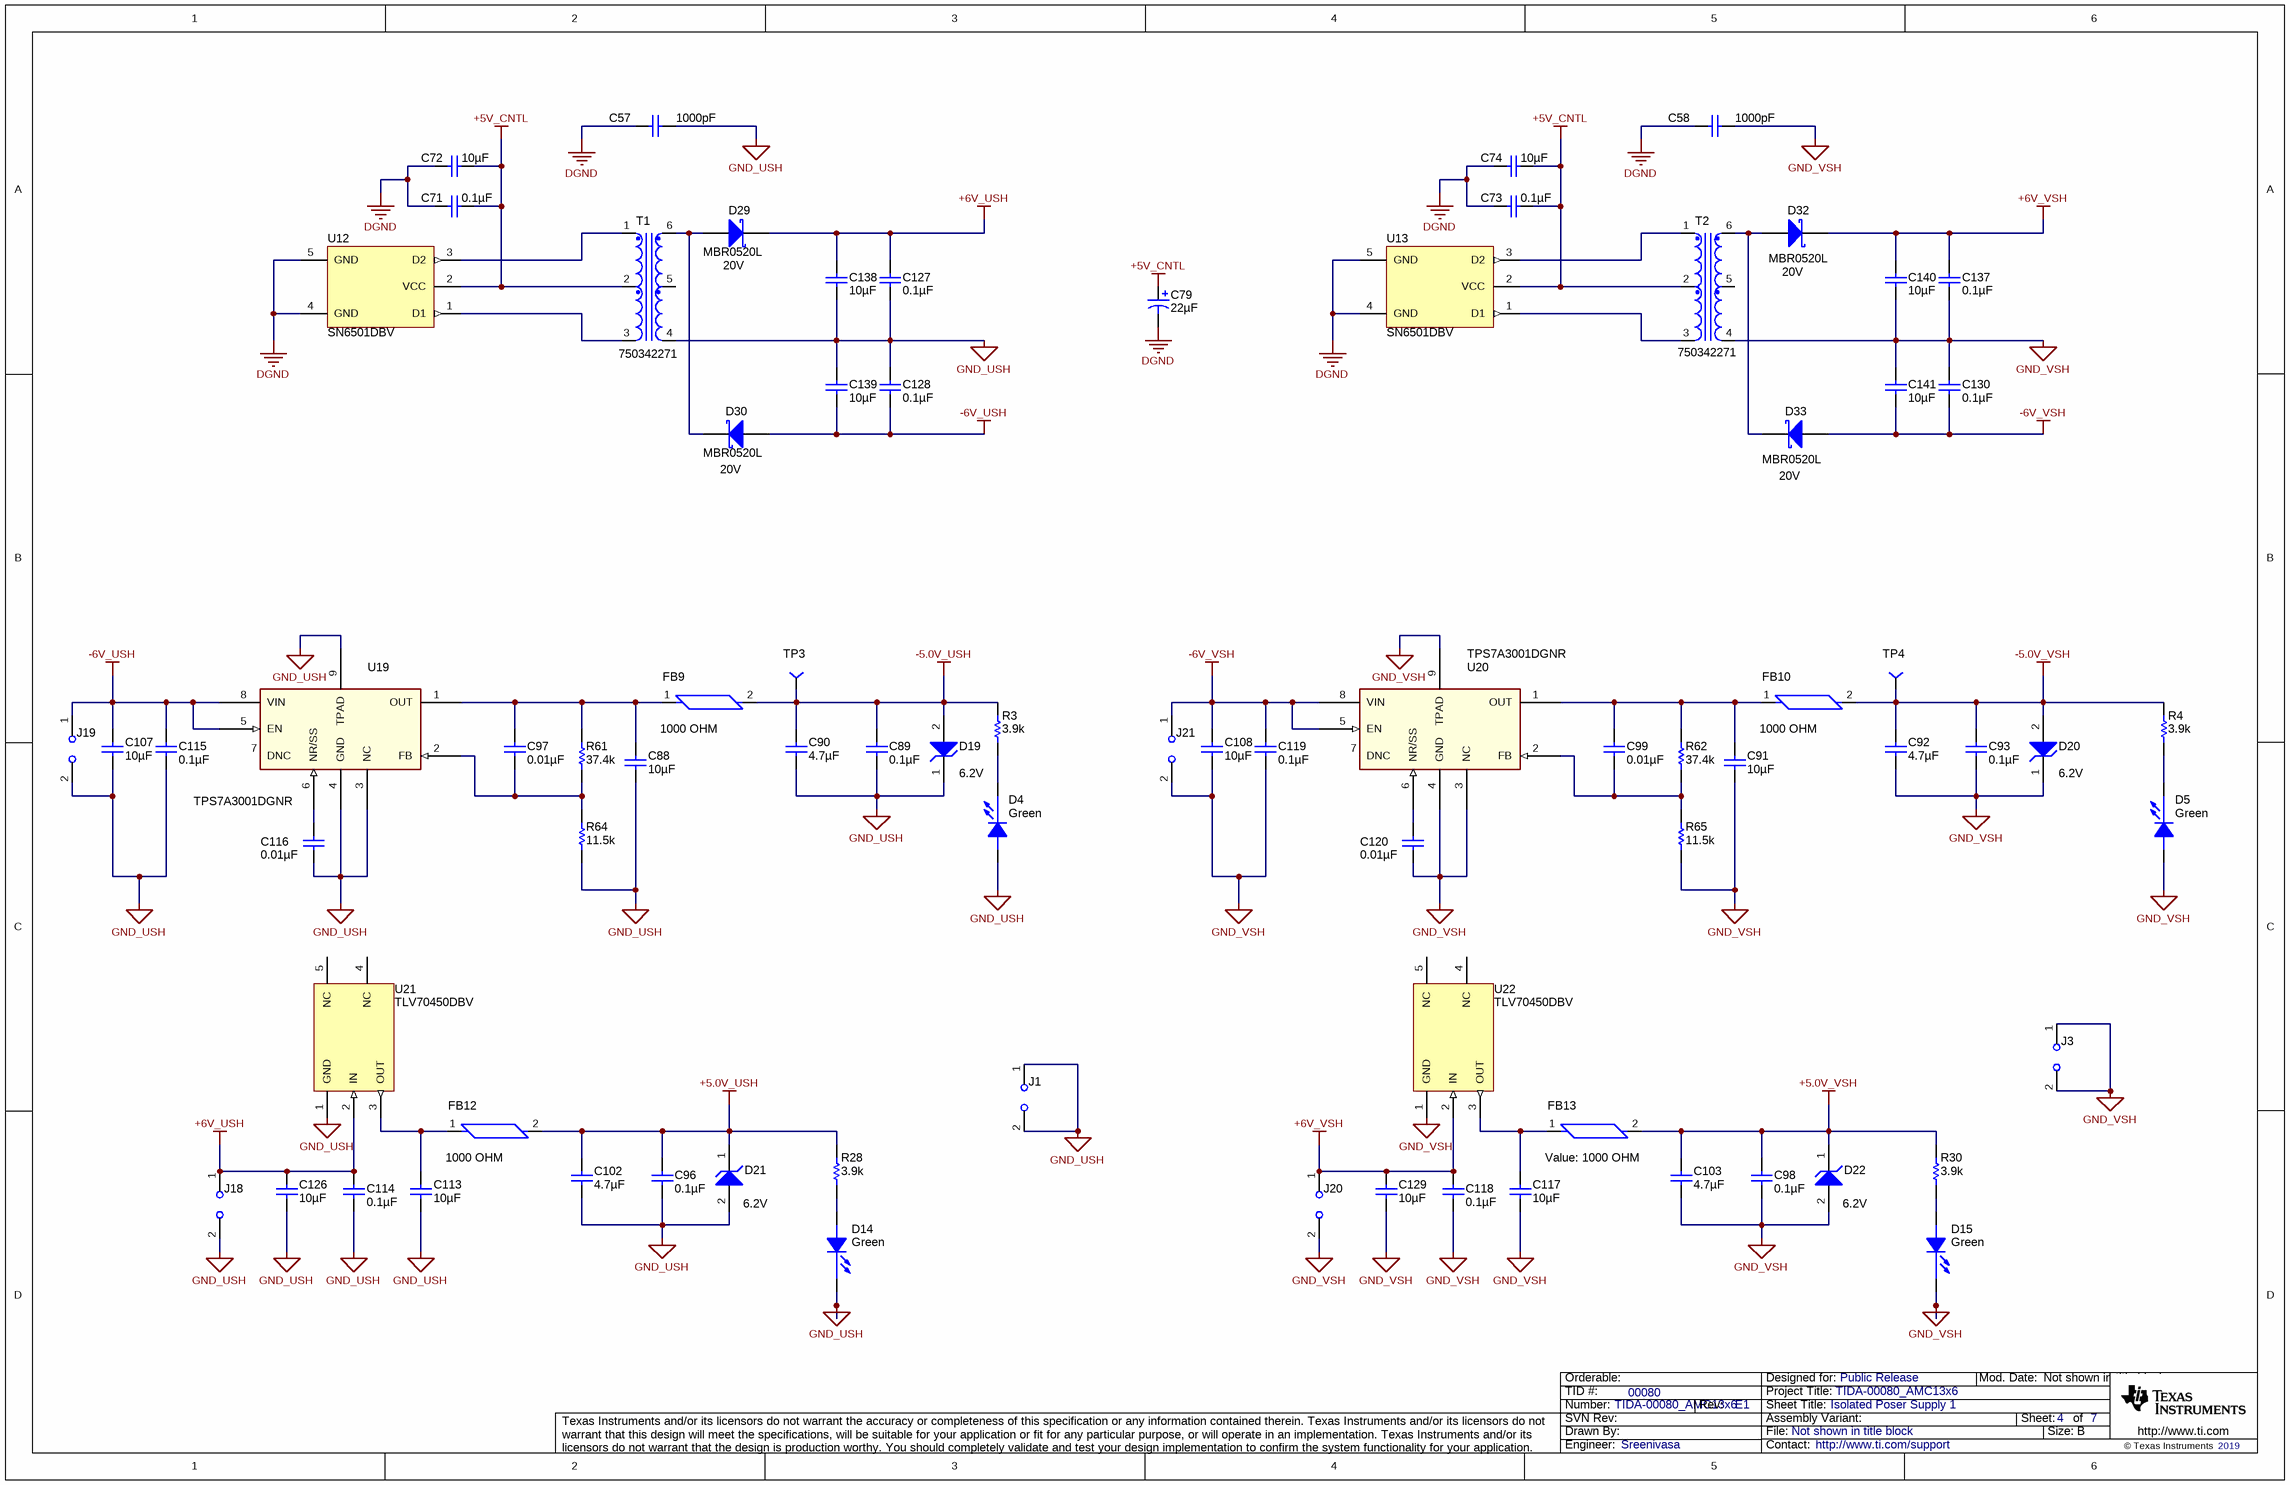
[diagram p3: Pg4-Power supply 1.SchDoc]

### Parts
C57  value 1000pF  [CAP_200mil]
C58  value 1000pF  [CAP_200mil]
C71  ValueDisplayed: 0.1µF  [0603]
C72  ValueDisplayed: 10µF  [1210]
C73  ValueDisplayed: 0.1µF  [0603]
C74  ValueDisplayed: 10µF  [1210]
C79  ValueDisplayed: 22µF  [SM_RADIAL_5MM]  (hidden comment: UUD1E220MCL1GS)
C88  ValueDisplayed: 10µF  [1210]
C89  ValueDisplayed: 0.1µF  [0603]
C90  ValueDisplayed: 4.7µF  [0805_HV]
C91  ValueDisplayed: 10µF  [1210]
C92  ValueDisplayed: 4.7µF  [0805_HV]
C93  ValueDisplayed: 0.1µF  [0603]
C96  ValueDisplayed: 0.1µF  [0603]
C97  ValueDisplayed: 0.01µF  [0603]
C98  ValueDisplayed: 0.1µF  [0603]
C99  ValueDisplayed: 0.01µF  [0603]
C102  ValueDisplayed: 4.7µF  [0805_HV]
C103  ValueDisplayed: 4.7µF  [0805_HV]
C107  ValueDisplayed: 10µF  [1210]
C108  ValueDisplayed: 10µF  [1210]
C113  ValueDisplayed: 10µF  [1210]
C114  ValueDisplayed: 0.1µF  [0603]
C115  ValueDisplayed: 0.1µF  [0603]
C116  ValueDisplayed: 0.01µF  [0603]
C117  ValueDisplayed: 10µF  [1210]
C118  ValueDisplayed: 0.1µF  [0603]
C119  ValueDisplayed: 0.1µF  [0603]
C120  ValueDisplayed: 0.01µF  [0603]
C126  ValueDisplayed: 10µF  [1210]
C127  ValueDisplayed: 0.1µF  [0603]
C128  ValueDisplayed: 0.1µF  [0603]
C129  ValueDisplayed: 10µF  [1210]
C130  ValueDisplayed: 0.1µF  [0603]
C137  ValueDisplayed: 0.1µF  [0603]
C138  ValueDisplayed: 10µF  [1210]
C139  ValueDisplayed: 10µF  [1210]
C140  ValueDisplayed: 10µF  [1210]
C141  ValueDisplayed: 10µF  [1210]
D4  value Green  [LED0603AA]
D5  value Green  [LED0603AA]
D14  value Green  [LED0603AA]
D15  value Green  [LED0603AA]
D19  value 6.2V  [powerDI123]
D20  value 6.2V  [powerDI123]
D21  value 6.2V  [powerDI123]
D22  value 6.2V  [powerDI123]
D29  MBR0520L  value 20V  [SOD-123]
D30  MBR0520L  value 20V  [SOD-123]
D32  MBR0520L  value 20V  [SOD-123]
D33  MBR0520L  value 20V  [SOD-123]
FB9  value 1000 OHM  [FB0603]
FB10  value 1000 OHM  [FB0603]
FB12  value 1000 OHM  [FB0603]
FB13  value 1000 OHM  [FB0603]
J1  (no value)  [HDR100_1X2]
J3  (no value)  [HDR100_1X2]
J18  (no value)  [HDR100_1X2]
J19  (no value)  [HDR100_1X2]
J20  (no value)  [HDR100_1X2]
J21  (no value)  [HDR100_1X2]
R3  value 3.9k  [0603]
R4  value 3.9k  [0603]
R28  value 3.9k  [0603]
R30  value 3.9k  [0603]
R61  value 37.4k  [0603]
R62  value 37.4k  [0603]
R64  value 11.5k  [0603]
R65  value 11.5k  [0603]
T1  750342271  [760390015]
T2  750342271  [760390015]
TP3  (no value)  [TP-040_RND]
TP4  (no value)  [TP-040_RND]
U12  SN6501DBV  [DBV0005A_N]
U13  SN6501DBV  [DBV0005A_N]
U19  TPS7A3001DGNR  [MSOP8(DGN)]
U20  (no value)  [MSOP8(DGN)]
U21  TLV70450DBV  [DBV0005A_N]
U22  TLV70450DBV  [DBV0005A_N]

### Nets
+5.0V_USH: C96.1 C102.2 D21.1(K) FB12.2 R28.2
+5.0V_VSH: C98.1 C103.2 D22.1(K) FB13.2 R30.2
+5V_CNTL: C71.2 C72.2 C73.2 C74.2 C79.1(+) T1.2 T2.2 U12.2(VCC) U13.2(VCC)
+6V_USH: C114.1 C126.2 C127.1 C138.1 D29.1(K) J18.1 U21.2(IN)
+6V_VSH: C118.1 C129.2 C137.1 C140.1 D32.1(K) J20.1 U22.2(IN)
-5.0V_USH: C89.1 C90.2 D19.2(A) FB9.2 R3.2 TP3.1
-5.0V_VSH: C92.2 C93.1 D20.2(A) FB10.2 R4.2 TP4.1
-6V_USH: C107.2 C115.1 C128.2 C139.2 D30.2(A) J19.1 U19.5(EN) U19.8(VIN)
-6V_VSH: C108.2 C119.1 C130.2 C141.2 D33.2(A) J21.1 U20.5(EN) U20.8(VIN)
DGND: C57.1 C58.1 C71.1 C72.1 C73.1 C74.1 C79.2(-) U12.4(GND) U12.5(GND) U13.4(GND) U13.5(GND)
GND_USH: C57.2 C88.1 C89.2 C90.1 C96.2 C102.1 C107.1 C113.1 C114.2 C115.2 C116.1 C126.1 C127.2 C128.1 C138.2 C139.1 D4.2(A) D14.1(C) D19.1(K) D21.2(A) J1.1 J1.2 J18.2 J19.2 R64.1 T1.4 U19.3(NC) U19.4(GND) U19.9(TPAD) U21.1(GND)
GND_VSH: C58.2 C91.1 C92.1 C93.2 C98.2 C103.1 C108.1 C117.1 C118.2 C119.2 C120.1 C129.1 C130.1 C137.2 C140.2 C141.1 D5.2(A) D15.1(C) D20.1(K) D22.2(A) J3.1 J3.2 J20.2 J21.2 R65.1 T2.4 U20.3(NC) U20.4(GND) U20.9(TPAD) U22.1(GND)
NetC88_2: C88.2 C97.2 FB9.1 R61.2 U19.1(OUT)
NetC91_2: C91.2 C99.2 FB10.1 R62.2 U20.1(OUT)
NetC97_1: C97.1 R61.1 R64.2 U19.2(FB)
NetC99_1: C99.1 R62.1 R65.2 U20.2(FB)
NetC113_2: C113.2 FB12.1 U21.3(OUT)
NetC116_2: C116.2 U19.6(NR/SS)
NetC117_2: C117.2 FB13.1 U22.3(OUT)
NetC120_2: C120.2 U20.6(NR/SS)
NetD4_1: D4.1(C) R3.1
NetD5_1: D5.1(C) R4.1
NetD14_2: D14.2(A) R28.1
NetD15_2: D15.2(A) R30.1
NetD29_2: D29.2(A) D30.1(K) T1.6
NetD32_2: D32.2(A) D33.1(K) T2.6
NetT1_1: T1.1 U12.3(D2)
NetT1_3: T1.3 U12.1(D1)
NetT2_1: T2.1 U13.3(D2)
NetT2_3: T2.3 U13.1(D1)

Not connected (* = marked no-connect by the designer): T1 5; T2 5; U19 7(DNC); U20 7(DNC); U21 4(NC) 5(NC); U22 4(NC) 5(NC)

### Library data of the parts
C57 C58 = 202R18W102KV4E: CAP CER 1000PF 1KV 10% RADIAL; PartNumber: S102K29Y5PN63J5R; Manufacturer: Vishay BC Components; Polarized: N; CompType: Capacitor; Tolerance_%: 0
C71 C73 C89 C93 C96 C98 C114 C115 C118 C119 C127 C128 C130 C137 = C0603C104K5RACTU: as C32 on sheet Pg2-Current Sense
C72 C74 C88 C91 C107 C108 C113 C117 C126 C129 C138-C141 = GMK325AB7106MM-T: as C17 on sheet Pg2-Current Sense
C79 = UUD1E220MCL1GS: as C80 on sheet Pg2-Current Sense
C90 C92 C102 C103 = C2012X5R1H475K125AB: CAP, CERM, 4.7uF, 50V, +/-10%, X5R, 0805; Manufacturer: TDK; Polarized: N; CompType: Capacitor; U/M: EA; Cap_F: 0.0000047; Tolerance_%: 10; Value1: Unknown; VDC_V: 50; TaMin_C: -55; TaMax_C: 85; Cap_Case: 0805
C97 C99 C116 C120 = 06031C103JAT2A: CAP, CERM, 0.01uF, 100V, +/-5%, X7R, 0603; PartNumber: 06031C103J4Z4A; Manufacturer: AVX; Polarized: N; CompType: Capacitor; U/M: EA; Cap_F: 0.00000001; Tolerance_%: 5; ESR_Ohm: 0.098; Value1: 0.098 ohm; VDC_V: 100; TaMin_C: -55; TaMax_C: 125
D4 D5 D14 D15 = LED_LG L29K-G2J1-24-Z: LED SmartLED Green 570NM; Manufacturer: OSRAM; SymbolCreator: x0120606
D19-D22 = DFLZ6V2-7: Diode, Zener, 6.2V, 1W, PowerDI123; Manufacturer: Diodes Inc.; U/M: EA; Power_W: 1; Vz_V: 6.2; RJA_CperW: 110
D29 D30 D32 D33 = MBR0520LT1G: Diode, Schottky, 20V, 0.5A, SOD-123; Manufacturer: Fairchild Semiconductor; U/M: EA; Vf_V: 0.385; Value2: 0.385V; Io_A: 0.5; Vr_V: 20; TJmax_C: 125; RJC_CperW: 150
FB9 FB10 FB12 FB13 = MMZ1608B102C: as FB2 on sheet Pg2-Current Sense
J1 J3 J18-J21 = JUMPER_2X100MIL: as J2 on sheet Pg2-Current Sense
R3 R4 R28 R30 = CRCW06033K90JNEA: RES, 3.9k ohm, 5%, 0.1W, 0603; Manufacturer: Vishay-Dale; CompType: Resistor; Res_ohm: 3900; Value_Code: 3k90; Tolerance_%: 5; Power_W: 0.1; VDC_V: 75; TempCo: 200 ppm/C; EIA_Code: E24; U/M: EA
R61 R62 = RT0603BRD0737KL: RES 37.4K OHM 1/10W .1% 0603 SMD; PartNumber: ERA-3AEB3742V; Manufacturer: Panasonic; CompType: Resistor; Res_ohm: 37000; Value_Code: 37k4; Tolerance_%: 1%; Power_W: 0.1; Value2: 0.1W; VDC_V: 75; TempCo: 25 ppm/C; EIA_Code: E192; U/M: EA
R64 R65 = CRCW060311K5FKEA: RES, 11.5k ohm, 1%, 0.1W, 0603; Manufacturer: Vishay-Dale; CompType: Resistor; Res_ohm: 11500; Value_Code: 11k5; Tolerance_%: 1; Power_W: 0.1; VDC_V: 75; TempCo: 100 ppm/C; EIA_Code: E96; U/M: EA
T1 T2 = TRNSFMR: Transformer 469uH SMD; Manufacturer: Wurth Electronics Midcom
TP3 TP4 = TP-040_RND: as TP6 on sheet Pg2-Current Sense
U12 U13 = SN6501DBV: Transformer Driver for Isolated Power Supplies, DBV0005A; Alternate Manufacturer: None; Manufacturer: Texas Instruments; SymbolCreator: a0411947; CompType: IC; U/M: EA
U19 U20 = TPS7A3001DGNR: -36V, -200mA, Ultralow-Noise, Negative Linear Regulator; Alternate Manufacturer: None; Manufacturer: Texas Instruments; CompType: IC; SymbolCreator: x0120606
U21 U22 = TLV70450DBV: Regulator, LDO, 5V, 0.15A, SOT23-5; Alternate Manufacturer: None; Manufacturer: Texas Instruments; SymbolCreator: x0120606; CompType: IC

## Sheet Pg5-Power supply 2.SchDoc: Isolated Poser Supply 2
size 431 x 279 mm; Date: Not shown in title block; ApprovedBy: Not shown in title block; CheckedBy: Not shown in title block; Author: Not shown in title block; CompanyName: Not shown in title block; Engineer: Not shown in title block; Organization: Not shown in title block; Address1: Not shown in title block; Address2: Not shown in title block; Address3: Not shown in title block; Address4: Not shown in title block; DocumentNumber: 6; Revision: Use project parameter SCH_Rev; SheetNumber: 5; SheetTotal: 7; PageSetup: Record=PageOptions¦CenterHorizontal=True¦CenterVertical=True¦PrintScale=1.00¦XCorrection=1.00¦YCorrection=1.00¦PrintKind=0¦BorderSize=5000000¦LeftOffset=0¦BottomOffset=0¦Orientation=2¦PaperLength=1000¦PaperWidth=1000¦Scale=100¦PaperSource=15¦PrintQuality=600¦MediaType=1¦DitherType=10¦PaperKind=Letter¦PrintScaleMode=1
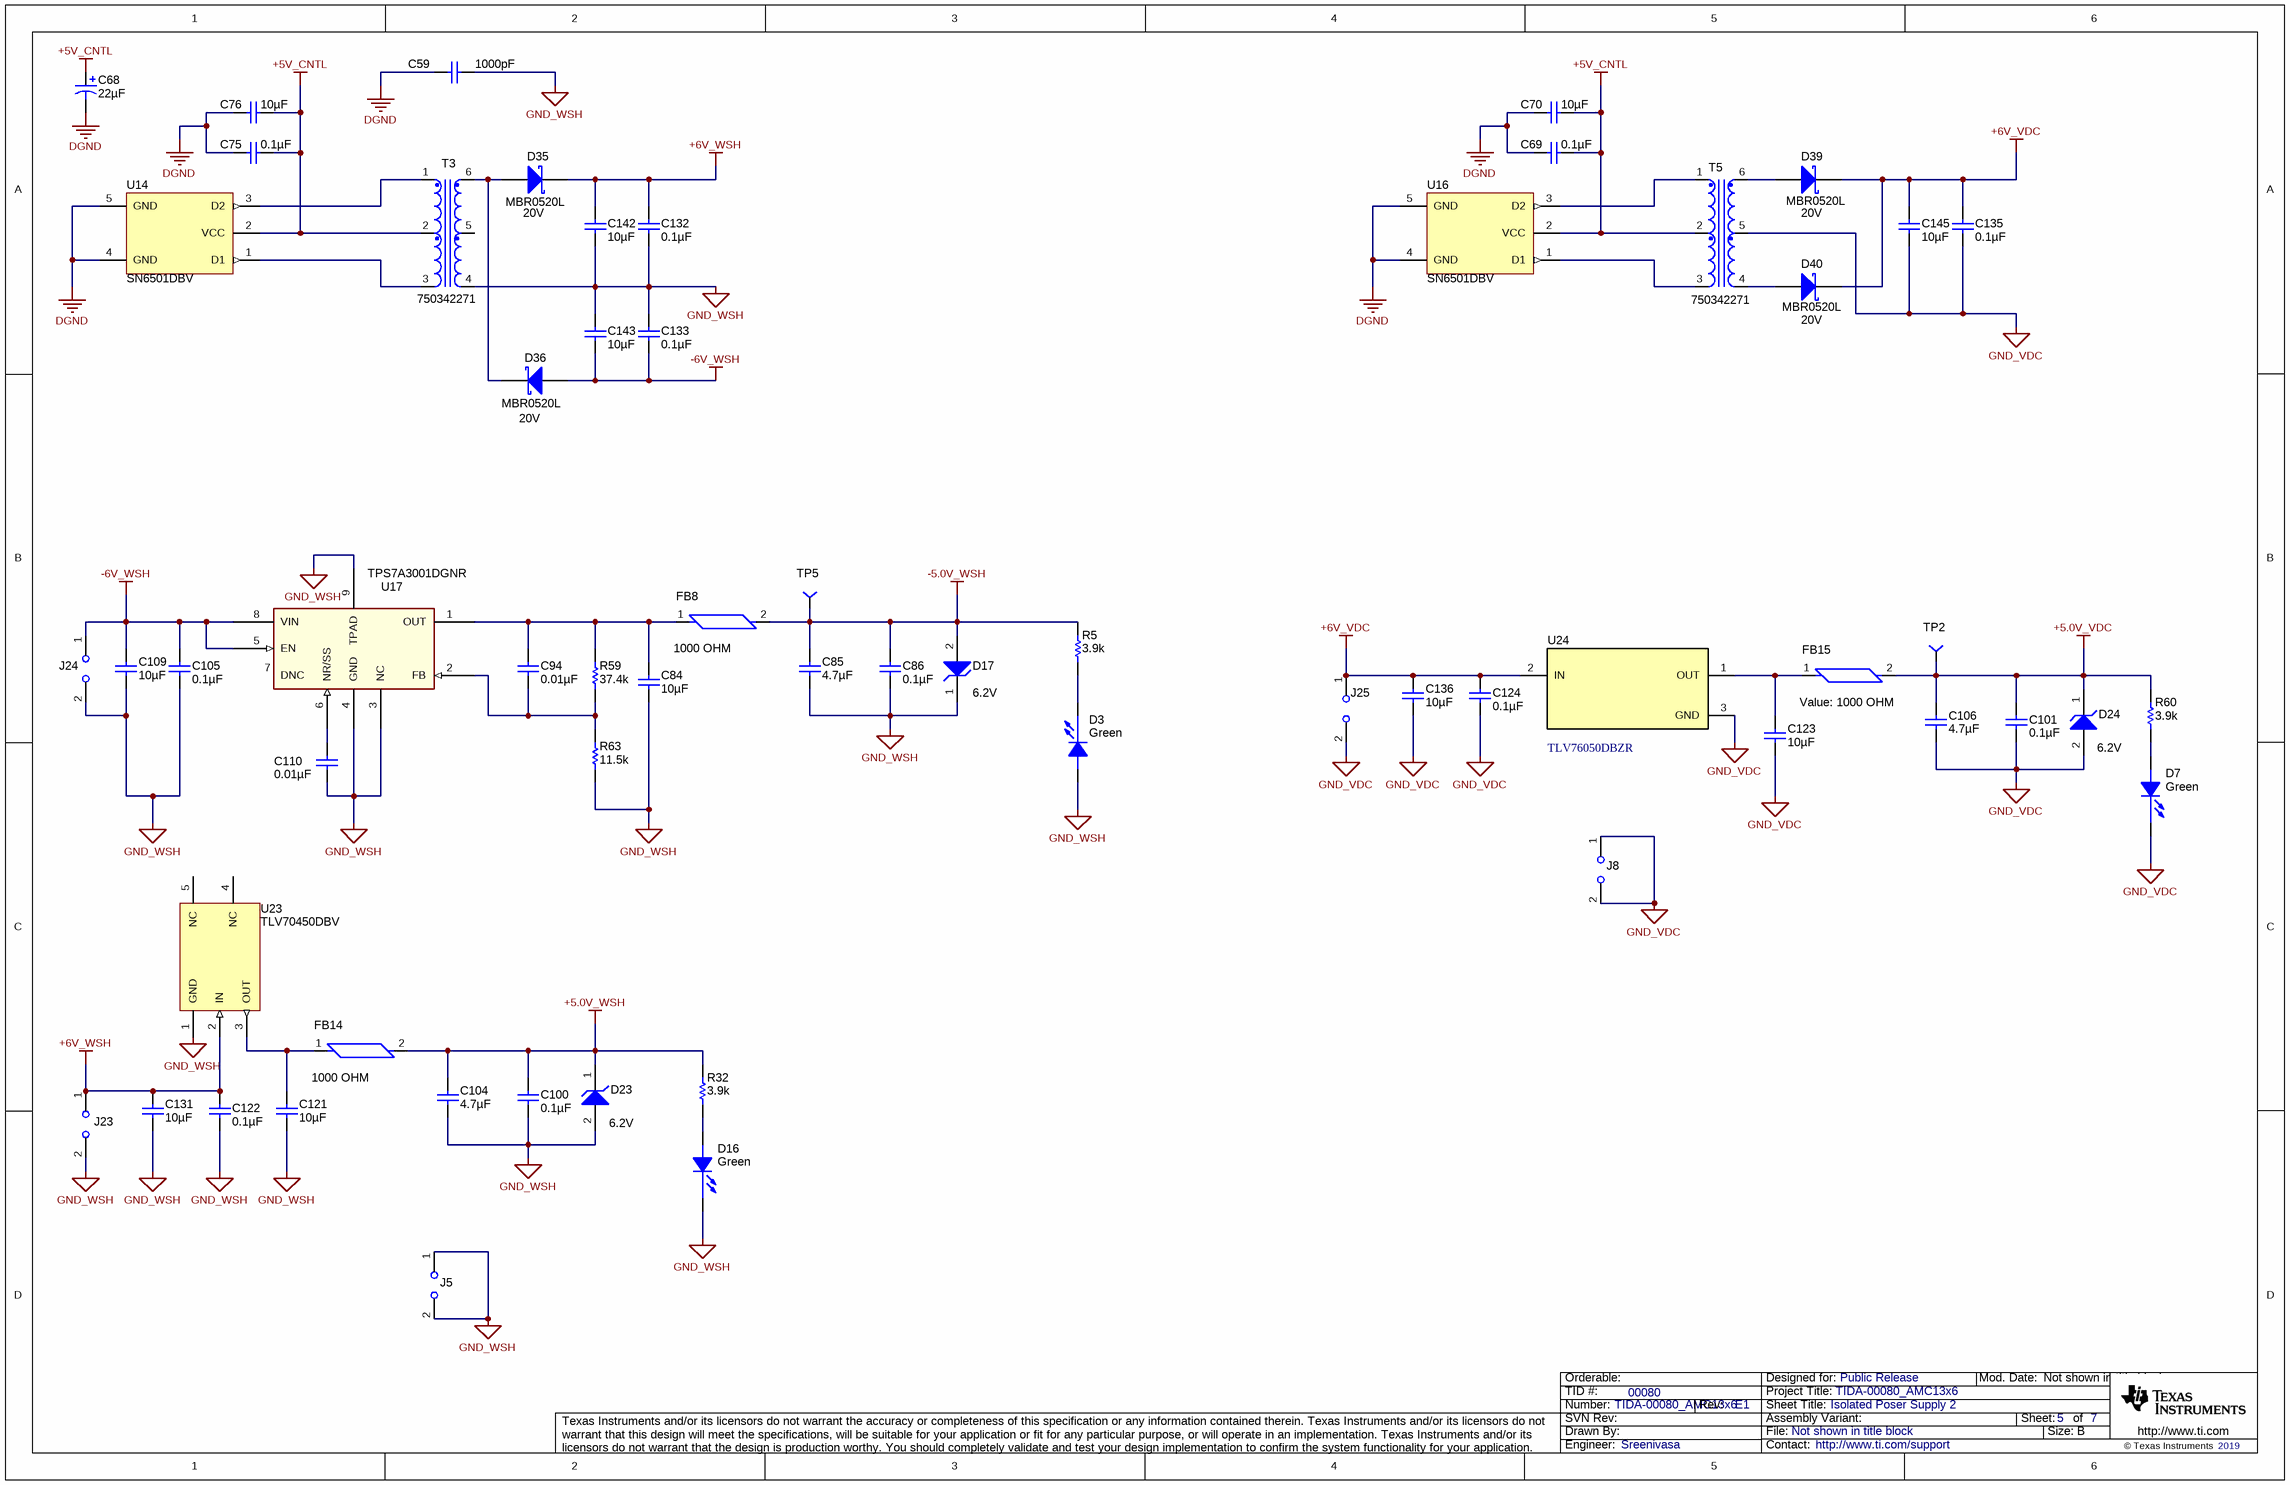
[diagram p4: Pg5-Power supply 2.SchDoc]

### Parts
C59  value 1000pF  [CAP_200mil]
C68  ValueDisplayed: 22µF  [SM_RADIAL_5MM]  (hidden comment: UUD1E220MCL1GS)
C69  ValueDisplayed: 0.1µF  [0603]
C70  ValueDisplayed: 10µF  [1210]
C75  ValueDisplayed: 0.1µF  [0603]
C76  ValueDisplayed: 10µF  [1210]
C84  ValueDisplayed: 10µF  [1210]
C85  ValueDisplayed: 4.7µF  [0805_HV]
C86  ValueDisplayed: 0.1µF  [0603]
C94  ValueDisplayed: 0.01µF  [0603]
C100  ValueDisplayed: 0.1µF  [0603]
C101  ValueDisplayed: 0.1µF  [0603]
C104  ValueDisplayed: 4.7µF  [0805_HV]
C105  ValueDisplayed: 0.1µF  [0603]
C106  ValueDisplayed: 4.7µF  [0805_HV]
C109  ValueDisplayed: 10µF  [1210]
C110  ValueDisplayed: 0.01µF  [0603]
C121  ValueDisplayed: 10µF  [1210]
C122  ValueDisplayed: 0.1µF  [0603]
C123  ValueDisplayed: 10µF  [1210]
C124  ValueDisplayed: 0.1µF  [0603]
C131  ValueDisplayed: 10µF  [1210]
C132  ValueDisplayed: 0.1µF  [0603]
C133  ValueDisplayed: 0.1µF  [0603]
C135  ValueDisplayed: 0.1µF  [0603]
C136  ValueDisplayed: 10µF  [1210]
C142  ValueDisplayed: 10µF  [1210]
C143  ValueDisplayed: 10µF  [1210]
C145  ValueDisplayed: 10µF  [1210]
D3  value Green  [LED0603AA]
D7  value Green  [LED0603AA]
D16  value Green  [LED0603AA]
D17  value 6.2V  [powerDI123]
D23  value 6.2V  [powerDI123]
D24  value 6.2V  [powerDI123]
D35  MBR0520L  value 20V  [SOD-123]
D36  MBR0520L  value 20V  [SOD-123]
D39  MBR0520L  value 20V  [SOD-123]
D40  MBR0520L  value 20V  [SOD-123]
FB8  value 1000 OHM  [FB0603]
FB14  value 1000 OHM  [FB0603]
FB15  value 1000 OHM  [FB0603]
J5  (no value)  [HDR100_1X2]
J8  (no value)  [HDR100_1X2]
J23  (no value)  [HDR100_1X2]
J24  (no value)  [HDR100_1X2]
J25  (no value)  [HDR100_1X2]
R5  value 3.9k  [0603]
R32  value 3.9k  [0603]
R59  value 37.4k  [0603]
R60  value 3.9k  [0603]
R63  value 11.5k  [0603]
T3  750342271  [760390015]
T5  750342271  [760390015]
TP2  (no value)  [TP-040_RND]
TP5  (no value)  [TP-040_RND]
U14  SN6501DBV  [DBV0005A_N]
U16  SN6501DBV  [DBV0005A_N]
U17  (no value)  [MSOP8(DGN)]
U23  TLV70450DBV  [DBV0005A_N]
U24  TLV76050DBZR  [DBZ0003A_N]

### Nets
+5.0V_VDC: C101.1 C106.2 D24.1(K) FB15.2 R60.2 TP2.1
+5.0V_WSH: C100.1 C104.2 D23.1(K) FB14.2 R32.2
+5V_CNTL: C68.1(+) C69.2 C70.2 C75.2 C76.2 T3.2 T5.2 U14.2(VCC) U16.2(VCC)
+6V_VDC: C124.1 C135.1 C136.2 C145.1 D39.1(K) D40.1(K) J25.1 U24.2(IN)
+6V_WSH: C122.1 C131.2 C132.1 C142.1 D35.1(K) J23.1 U23.2(IN)
-5.0V_WSH: C85.2 C86.1 D17.2(A) FB8.2 R5.2 TP5.1
-6V_WSH: C105.1 C109.2 C133.2 C143.2 D36.2(A) J24.1 U17.5(EN) U17.8(VIN)
DGND: C59.1 C68.2(-) C69.1 C70.1 C75.1 C76.1 U14.4(GND) U14.5(GND) U16.4(GND) U16.5(GND)
GND_VDC: C101.2 C106.1 C123.1 C124.2 C135.2 C136.1 C145.2 D7.1(C) D24.2(A) J8.1 J8.2 J25.2 T5.5 U24.3(GND)
GND_WSH: C59.2 C84.1 C85.1 C86.2 C100.2 C104.1 C105.2 C109.1 C110.1 C121.1 C122.2 C131.1 C132.2 C133.1 C142.2 C143.1 D3.2(A) D16.1(C) D17.1(K) D23.2(A) J5.1 J5.2 J23.2 J24.2 R63.1 T3.4 U17.3(NC) U17.4(GND) U17.9(TPAD) U23.1(GND)
NetC84_2: C84.2 C94.2 FB8.1 R59.2 U17.1(OUT)
NetC94_1: C94.1 R59.1 R63.2 U17.2(FB)
NetC110_2: C110.2 U17.6(NR/SS)
NetC121_2: C121.2 FB14.1 U23.3(OUT)
NetC123_2: C123.2 FB15.1 U24.1(OUT)
NetD3_1: D3.1(C) R5.1
NetD7_2: D7.2(A) R60.1
NetD16_2: D16.2(A) R32.1
NetD35_2: D35.2(A) D36.1(K) T3.6
NetD39_2: D39.2(A) T5.6
NetD40_2: D40.2(A) T5.4
NetT3_1: T3.1 U14.3(D2)
NetT3_3: T3.3 U14.1(D1)
NetT5_1: T5.1 U16.3(D2)
NetT5_3: T5.3 U16.1(D1)

Not connected (* = marked no-connect by the designer): T3 5; U17 7(DNC); U23 4(NC) 5(NC)

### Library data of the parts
C59 = 202R18W102KV4E: as C57 on sheet Pg4-Power supply 1
C68 = UUD1E220MCL1GS: as C80 on sheet Pg2-Current Sense
C69 C75 C86 C100 C101 C105 C122 C124 C132 C133 C135 = C0603C104K5RACTU: as C32 on sheet Pg2-Current Sense
C70 C76 C84 C109 C121 C123 C131 C136 C142 C143 C145 = GMK325AB7106MM-T: as C17 on sheet Pg2-Current Sense
C85 C104 C106 = C2012X5R1H475K125AB: as C90 on sheet Pg4-Power supply 1
C94 C110 = 06031C103JAT2A: CAP, CERM, 0.01uF, 100V, +/-5%, X7R, 0603; Manufacturer: AVX; Polarized: N; CompType: Capacitor; U/M: EA; Cap_F: 0.00000001; Tolerance_%: 5; ESR_Ohm: 0.098; Value1: 0.098 ohm; VDC_V: 100; TaMin_C: -55; TaMax_C: 125
D3 D7 D16 = LED_LG L29K-G2J1-24-Z: as D4 on sheet Pg4-Power supply 1
D17 D23 D24 = DFLZ6V2-7: as D19 on sheet Pg4-Power supply 1
D35 D36 D39 D40 = MBR0520LT1G: as D29 on sheet Pg4-Power supply 1
FB8 FB14 FB15 = MMZ1608B102C: as FB2 on sheet Pg2-Current Sense
J5 J8 J23-J25 = JUMPER_2X100MIL: as J2 on sheet Pg2-Current Sense
R5 R32 R60 = CRCW06033K90JNEA: as R3 on sheet Pg4-Power supply 1
R59 = RT0603BRD0737KL: RES 37.4K OHM 1/10W .1% 0603 SMD; PartNumber: ERA-3AEB3742V; Manufacturer: Panasonic; CompType: Resistor; Res_ohm: 37000; Value_Code: 37k4; Tolerance_%: 0.1; Value1: 1%; Value2: 0.1W; VDC_V: 75; TempCo: 25 ppm/C; EIA_Code: E192; U/M: EA
R63 = CRCW060311K5FKEA: as R64 on sheet Pg4-Power supply 1
T3 T5 = TRNSFMR: as T1 on sheet Pg4-Power supply 1
TP2 TP5 = TP-040_RND: as TP6 on sheet Pg2-Current Sense
U14 U16 = SN6501DBV: as U12 on sheet Pg4-Power supply 1
U17 = TPS7A3001DGNR: as U19 on sheet Pg4-Power supply 1
U23 = TLV70450DBV: as U21 on sheet Pg4-Power supply 1
U24 = CMP-0074892-1: 100-mA, 30-V, Fixed-Output, Linear-Voltage Regulator, DBZ0003A (SOT-23-3); Alternate PartNumber: TLV76050DBZT; Alternate Manufacturer: Texas Instruments; SizeAreaWB_mm2: 14.0; SizeZ_mm: 1.12; SizeX_mm: 2.5; SizeY_mm: 3.0; SizeArea_mm2: 7.5; CompType: IC; AEC Qualified: N; AEC Category: Q200

## Sheet Pg6-Power supply 3.SchDoc: Isolated Poser Supply 3
size 431 x 279 mm; Date: Not shown in title block; ApprovedBy: Not shown in title block; CheckedBy: Not shown in title block; Author: Not shown in title block; CompanyName: Not shown in title block; Engineer: Not shown in title block; Organization: Not shown in title block; Address1: Not shown in title block; Address2: Not shown in title block; Address3: Not shown in title block; Address4: Not shown in title block; DocumentNumber: 6; Revision: Use project parameter SCH_Rev; SheetNumber: 6; SheetTotal: 7; PageSetup: Record=PageOptions¦CenterHorizontal=True¦CenterVertical=True¦PrintScale=1.00¦XCorrection=1.00¦YCorrection=1.00¦PrintKind=0¦BorderSize=5000000¦LeftOffset=0¦BottomOffset=0¦Orientation=2¦PaperLength=1000¦PaperWidth=1000¦Scale=100¦PaperSource=15¦PrintQuality=600¦MediaType=1¦DitherType=10¦PaperKind=Letter¦PrintScaleMode=1
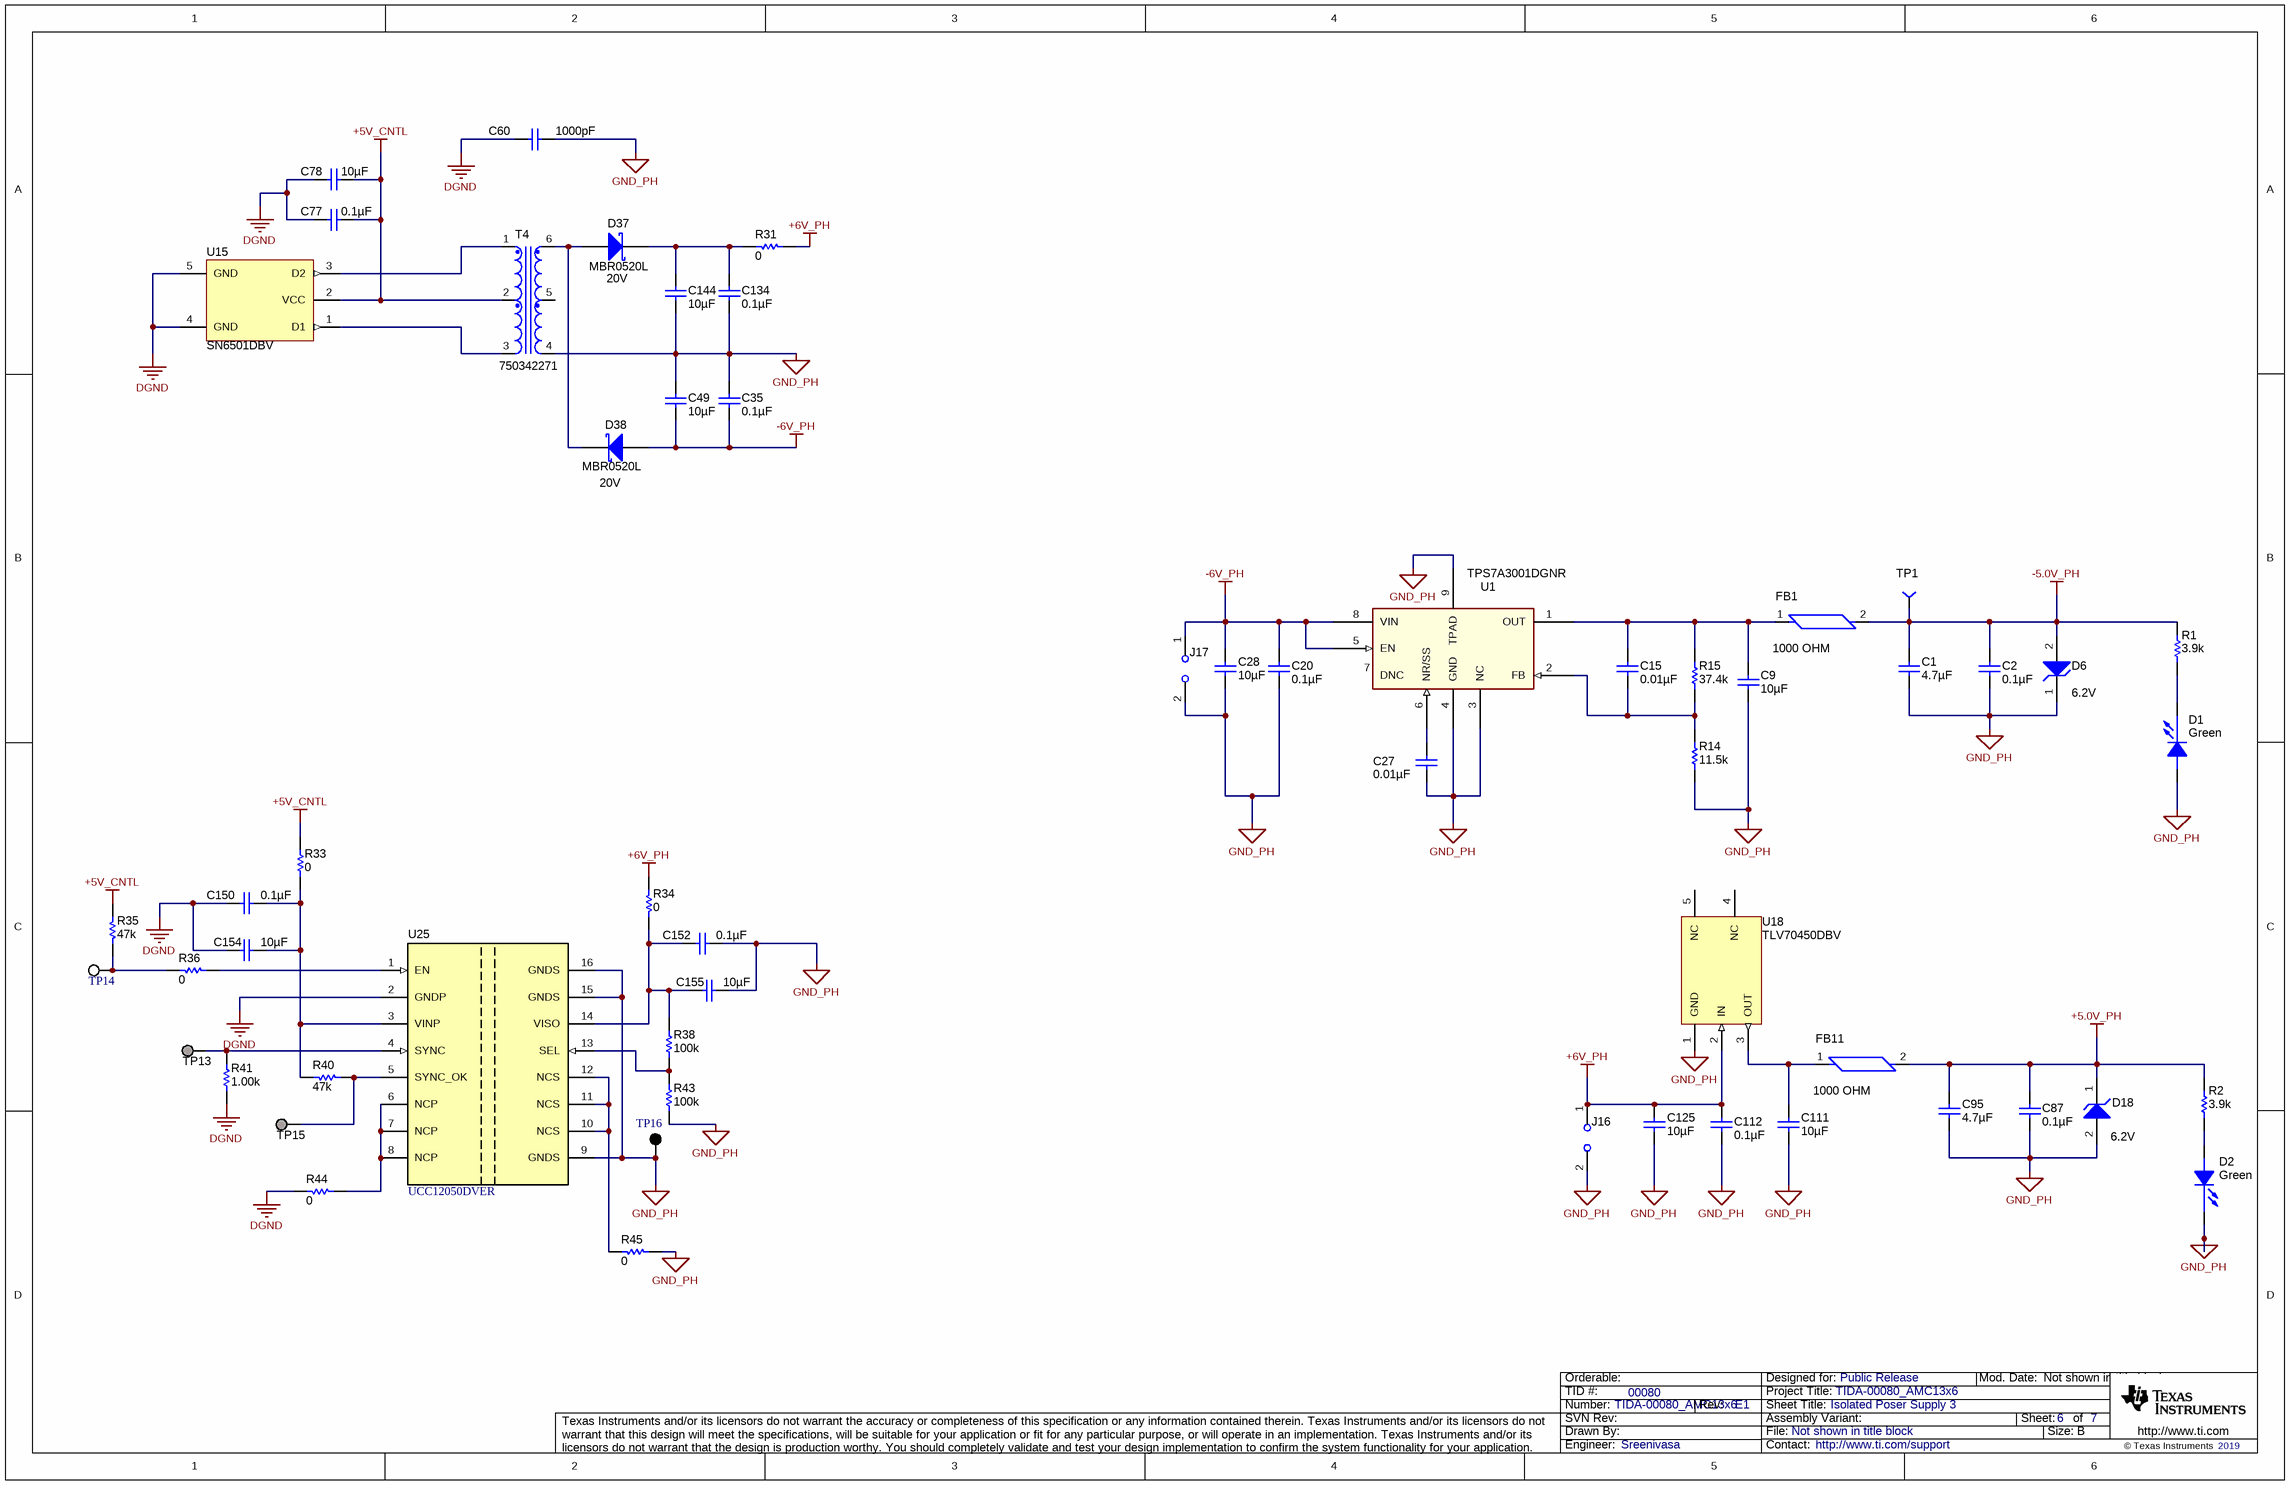
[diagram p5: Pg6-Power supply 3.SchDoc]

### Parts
C1  ValueDisplayed: 4.7µF  [0805_HV]
C2  ValueDisplayed: 0.1µF  [0603]
C9  ValueDisplayed: 10µF  [1210]
C15  ValueDisplayed: 0.01µF  [0603]
C20  ValueDisplayed: 0.1µF  [0603]
C27  ValueDisplayed: 0.01µF  [0603]
C28  ValueDisplayed: 10µF  [1210]
C35  ValueDisplayed: 0.1µF  [0603]
C49  ValueDisplayed: 10µF  [1210]
C60  value 1000pF  [CAP_200mil]
C77  ValueDisplayed: 0.1µF  [0603]
C78  ValueDisplayed: 10µF  [1210]
C87  ValueDisplayed: 0.1µF  [0603]
C95  ValueDisplayed: 4.7µF  [0805_HV]
C111  ValueDisplayed: 10µF  [1210]
C112  ValueDisplayed: 0.1µF  [0603]
C125  ValueDisplayed: 10µF  [1210]
C134  ValueDisplayed: 0.1µF  [0603]
C144  ValueDisplayed: 10µF  [1210]
C150  ValueDisplayed: 0.1µF  [0603]  (hidden comment: C0603C104K5RACTU)
C152  ValueDisplayed: 0.1µF  [0603]  (hidden comment: C0603C104K5RACTU)
C154  ValueDisplayed: 10µF  [1206_180]  (hidden comment: GRM31CR61H106KA12L)
C155  ValueDisplayed: 10µF  [1206_180]  (hidden comment: GRM31CR61H106KA12L)
D1  value Green  [LED0603AA]
D2  value Green  [LED0603AA]
D6  value 6.2V  [powerDI123]
D18  value 6.2V  [powerDI123]
D37  MBR0520L  value 20V  [SOD-123]
D38  MBR0520L  value 20V  [SOD-123]
FB1  value 1000 OHM  [FB0603]
FB11  value 1000 OHM  [FB0603]
J16  (no value)  [HDR100_1X2]
J17  (no value)  [HDR100_1X2]
R1  value 3.9k  [0603]
R2  value 3.9k  [0603]
R14  value 11.5k  [0603]
R15  value 37.4k  [0603]
R31  value 0  [0402M]  (hidden comment: RC0402JR-070RL)
R33  ValueDisplayed: 0  [0603]  (hidden comment: CRCW06030000Z0EA)
R34  ValueDisplayed: 0  [0603]  (hidden comment: CRCW06030000Z0EA)
R35  ValueDisplayed: 47k  [0603]  (hidden comment: RC0603JR-0747KL)
R36  value 0  [0402M]  (hidden comment: RC0402JR-070RL)
R38  ValueDisplayed: 100k  [0603]  (hidden comment: CRCW0603100KFKEA)
R40  ValueDisplayed: 47k  [0603]  (hidden comment: RC0603JR-0747KL)
R41  ValueDisplayed: 1.00k  [0402]  (hidden comment: ERJ-2RKF1001X)
R43  ValueDisplayed: 100k  [0603]  (hidden comment: CRCW0603100KFKEA)
R44  value 0  [0402M]  (hidden comment: RC0402JR-070RL)
R45  value 0  [0402M]  (hidden comment: RC0402JR-070RL)
T4  750342271  [760390015]
TP1  (no value)  [TP-040_RND]
TP13  Pogo Pad  [PogoPad]  (value not drawn)  (no BOM)
TP14  5002  [Keystone5002]  (value not drawn)
TP15  Pogo Pad  [PogoPad]  (value not drawn)  (no BOM)
TP16  5001  [Keystone5001]  (value not drawn)
U1  (no value)  [MSOP8(DGN)]
U15  SN6501DBV  [DBV0005A_N]
U18  TLV70450DBV  [DBV0005A_N]
U25  UCC12050DVER  [DVE0016A]

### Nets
+5.0V_PH: C87.1 C95.2 D18.1(K) FB11.2 R2.2
+5V_CNTL: C77.2 C78.2 R33.2 R35.2 T4.2 U15.2(VCC)
+6V_PH: C112.1 C125.2 J16.1 R31.1 R34.2 U18.2(IN)
-5.0V_PH: C1.2 C2.1 D6.2(A) FB1.2 R1.2 TP1.1
-6V_PH: C20.1 C28.2 C35.2 C49.2 D38.2(A) J17.1 U1.5(EN) U1.8(VIN)
DGND: C60.1 C77.1 C78.1 C150.1 C154.2 R41.1 R44.2 U15.4(GND) U15.5(GND) U25.2(GNDP)
GND_PH: C1.1 C2.2 C9.1 C20.2 C27.1 C28.1 C35.1 C49.1 C60.2 C87.2 C95.1 C111.1 C112.2 C125.1 C134.2 C144.2 C152.1 C155.1 D1.2(A) D2.1(C) D6.1(K) D18.2(A) J16.2 J17.2 R14.1 R43.1 R45.1 T4.4 TP16.1 U1.3(NC) U1.4(GND) U1.9(TPAD) U18.1(GND) U25.9(GNDS) U25.15(GNDS) U25.16(GNDS)
NetC9_2: C9.2 C15.2 FB1.1 R15.2 U1.1(OUT)
NetC15_1: C15.1 R14.2 R15.1 U1.2(FB)
NetC27_2: C27.2 U1.6(NR/SS)
NetC111_2: C111.2 FB11.1 U18.3(OUT)
NetC134_1: C134.1 C144.1 D37.1(K) R31.2
NetC150_2: C150.2 C154.1 R33.1 R40.2 U25.3(VINP)
NetC152_2: C152.2 C155.2 R34.1 R38.1 U25.14(VISO)
NetD1_1: D1.1(C) R1.1
NetD2_2: D2.2(A) R2.1
NetD37_2: D37.2(A) D38.1(K) T4.6
NetR35_1: R35.1 R36.2 TP14.1
NetR36_1: R36.1 U25.1(EN)
NetR38_2: R38.2 R43.2 U25.13(SEL)
NetR40_1: R40.1 TP15.1 U25.5(SYNC_OK)
NetR41_2: R41.2 TP13.1 U25.4(SYNC)
NetR44_1: R44.1 U25.6(NCP) U25.7(NCP) U25.8(NCP)
NetR45_2: R45.2 U25.10(NCS) U25.11(NCS) U25.12(NCS)
NetT4_1: T4.1 U15.3(D2)
NetT4_3: T4.3 U15.1(D1)

Not connected (* = marked no-connect by the designer): T4 5; U1 7(DNC); U18 4(NC) 5(NC)

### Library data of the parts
C1 C95 = C2012X5R1H475K125AB: as C90 on sheet Pg4-Power supply 1
C2 C20 C35 C77 C87 C112 C134 C150 C152 = C0603C104K5RACTU: as C32 on sheet Pg2-Current Sense
C9 C28 C49 C78 C111 C125 C144 = GMK325AB7106MM-T: as C17 on sheet Pg2-Current Sense
C15 C27 = 06031C103JAT2A: as C94 on sheet Pg5-Power supply 2
C60 = 202R18W102KV4E: as C57 on sheet Pg4-Power supply 1
C154 C155 = GRM31CR61H106KA12L: CAP, CERM, 10 µF, 50 V, +/- 10%, X5R, 1206; Manufacturer: MuRata; Polarized: N; CompType: Capacitor; Value: 10uF; U/M: EA; Cap_F: 0.00001; Tolerance_%: 10; Value1: Unknown; VDC_V: 50; Value2: 50V; TaMin_C: -55; TaMax_C: 85; Cap_Case: 1206; SizeArea_mm2: 5.12; SizeAreaWB_mm2: 10.92; SizeX_mm: 3.2; SizeY_mm: 1.6; SizeZ_mm: 1.8; AEC Category: Q200
D1 D2 = LED_LG L29K-G2J1-24-Z: as D4 on sheet Pg4-Power supply 1
D6 D18 = DFLZ6V2-7: as D19 on sheet Pg4-Power supply 1
D37 D38 = MBR0520LT1G: as D29 on sheet Pg4-Power supply 1
FB1 FB11 = MMZ1608B102C: as FB2 on sheet Pg2-Current Sense
J16 J17 = JUMPER_2X100MIL: as J2 on sheet Pg2-Current Sense
R1 R2 = CRCW06033K90JNEA: as R3 on sheet Pg4-Power supply 1
R14 = CRCW060311K5FKEA: as R64 on sheet Pg4-Power supply 1
R15 = RT0603BRD0737KL: as R59 on sheet Pg5-Power supply 2
R31 R36 R44 R45 = RC0402JR-070RL: RES, 0 ohm, 5%, 0.063W, 0402; Manufacturer: Yageo America; CompType: Resistor; Value_Code: 0000; Tolerance_%: 5; Power_W: 0.063; VDC_V: 50; TempCo: 200 ppm/C; EIA_Code: E24; U/M: EA
R33 R34 = CRCW06030000Z0EA: RES, 0, 5%, 0.1 W, 0603; Manufacturer: Vishay-Dale; CompType: Resistor; Value: 0; Value_Code: 0000; Tolerance_%: 5; Power_W: 0.1; Value2: 0.1W; VDC_V: 75; TempCo: 200 ppm/C; EIA_Code: E24; U/M: EA
R35 R40 = RC0603JR-0747KL: RES, 47 k, 5%, 0.1 W, 0603; Manufacturer: Yageo America; CompType: Resistor; Value: 47k; Res_ohm: 47000; Value_Code: 47k0; Tolerance_%: 5; Power_W: 0.1; Value2: 0.1W; VDC_V: 50; TempCo: 100 ppm/C; EIA_Code: E24; U/M: EA
R38 R43 = CRCW0603100KFKEA: RES, 100 k, 1%, 0.1 W, 0603; Manufacturer: Vishay-Dale; CompType: Resistor; Value: 100k; Res_ohm: 100000; Tolerance_%: 1; Power_W: 0.1; Value2: 0.1W; VDC_V: 75; TempCo: 100 ppm/C; SizeArea_mm2: 1.28; SizeX_mm: 1.6; SizeY_mm: 0.8; EIA_Code: E96; U/M: EA; AEC Category: Q200; Green_Lifecycle: Active; Green_REACh: Passed
R41 = ERJ-2RKF1001X: RES, 1.00 k, 1%, 0.1 W, 0402; Manufacturer: Panasonic; CompType: Resistor; Value: 1.00k; Res_ohm: 1000; Value_Code: 1k00; Tolerance_%: 1; Power_W: 0.1; Value2: 0.1W; VDC_V: 50; TempCo: 100 ppm/C; SizeArea_mm2: 0.5; SizeZ_mm: 0.6; EIA_Code: E96; U/M: EA; AEC Category: Q200; Green_Lifecycle: Active; Green_REACh: Passed
T4 = TRNSFMR: as T1 on sheet Pg4-Power supply 1
TP1 = TP-040_RND: as TP6 on sheet Pg2-Current Sense
TP13 TP15 = PogoPad: Pad for Pogo Pin Connector; SymbolCreator: codlsc
TP14 = 5002: Test Point, Miniature, White, TH; Manufacturer: Keystone; CompType: Test Point Loop; ContactFinish: Silver; Green_Lifecycle: Active; Green_REACh: Passed
TP16 = 5001: Test Point, Miniature, Black, TH; Manufacturer: Keystone; CompType: Test Point Loop; ContactFinish: Silver; Green_Lifecycle: Active; Green_REACh: Passed
U1 = TPS7A3001DGNR: as U19 on sheet Pg4-Power supply 1
U15 = SN6501DBV: as U12 on sheet Pg4-Power supply 1
U18 = TLV70450DBV: as U21 on sheet Pg4-Power supply 1
U25 = CMP-0081958-3: 500 mW, High-Efficiency, Low-Emissions, 5 kVRMS Isolated DC-DC Converter, DVE0016A (SO-MOD-16); Manufacturer: Texas Instruments; AEC Category: Q200; CompType: IC; SizeAreaWB_mm2: 151.29; SizeZ_mm: 2.65; AEC Qualified: N; SizeArea_mm2: 106.09; SizeY_mm: 10.3

## Sheet Pg7-Hardware.SchDoc: Hardware - MIiscellaneous
size 431 x 279 mm; Date: Not shown in title block; ApprovedBy: Not shown in title block; CheckedBy: Not shown in title block; Author: Not shown in title block; CompanyName: Not shown in title block; Engineer: Not shown in title block; Organization: Not shown in title block; Address1: Not shown in title block; Address2: Not shown in title block; Address3: Not shown in title block; Address4: Not shown in title block; DocumentNumber: 7; Revision: Use project parameter SCH_Rev; SheetNumber: 7; SheetTotal: 7; PageSetup: Record=PageOptions¦CenterHorizontal=True¦CenterVertical=True¦PrintScale=0.62¦XCorrection=1.00¦YCorrection=1.00¦PrintKind=0¦BorderSize=5000000¦LeftOffset=0¦BottomOffset=0¦Orientation=2¦PaperLength=1000¦PaperWidth=1000¦Scale=100¦PaperSource=15¦PrintQuality=600¦MediaType=1¦DitherType=10¦PaperKind=Letter¦PrintScaleMode=1
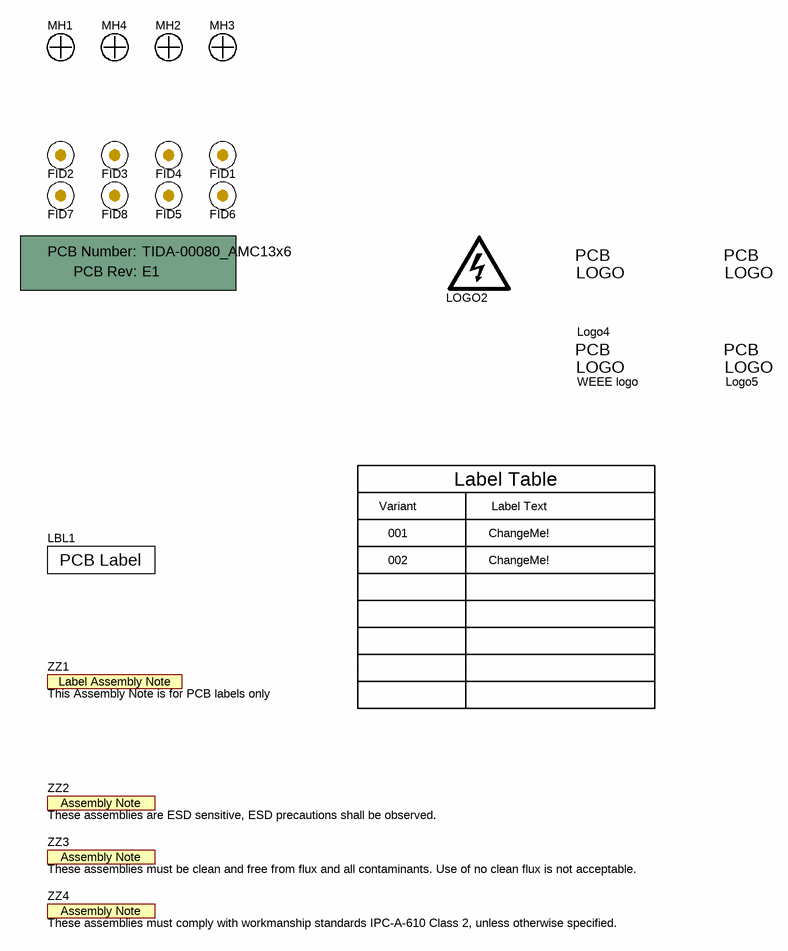
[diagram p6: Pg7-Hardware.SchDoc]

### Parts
!PCB1  (no value)  (mechanical)
FID1  (no value)  [Fiducial10-20]
FID2  (no value)  [Fiducial10-20]
FID3  (no value)  [Fiducial10-20]
FID4  (no value)  [Fiducial10-20]
FID5  (no value)  [Fiducial10-20]
FID6  (no value)  [Fiducial10-20]
FID7  (no value)  [Fiducial10-20]
FID8  (no value)  [Fiducial10-20]
LBL1  (no value)  [Label_650x200]
Logo1  Pb-Free Symbol  [Pb-Free_Overlay_Small]  (value not drawn)  (no BOM)
LOGO2  DANGER HIGH VOLTAGE  [IEC_HighVoltage_Medium]  (value not drawn)  (no BOM)
Logo3  FCC disclaimer  [FCC_disclaimer]  (value not drawn)  (no BOM)
Logo4  WEEE logo  [WEEE_Minimum]  (no BOM)
Logo5  ESD Susceptible  [ESD_Overlay_small]  (value not drawn)  (no BOM)
MH1  (no value)  [MH3.2]
MH2  (no value)  [MH3.2]
MH3  (no value)  [MH3.2]
MH4  (no value)  [MH3.2]
ZZ1  This Assembly Note is for PCB labels only  [AssemblyNoteLabel]  (no BOM)
ZZ2  These assemblies are ESD sensitive, ESD precautions shall be observed.  [AssemblyNote]  (no BOM)
ZZ3  These assemblies must be clean and free from flux and all contaminants. Use of no clean flux is not acceptable.  [AssemblyNote]  (no BOM)
ZZ4  These assemblies must comply with workmanship standards IPC-A-610 Class 2, unless otherwise specified.  [AssemblyNote]  (no BOM)

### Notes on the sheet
- Variant
- Label Table
- Label Text
- 001
- 002
- ChangeMe!

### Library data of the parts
!PCB1 = PCB: Printed Circuit Board; Manufacturer: Any; PartNumber: TIDA-00080_AMC13x6; SymbolCreator: a0412235
FID1-FID8 = Fiducial: Fiducial mark.  There is nothing to buy or mount.; SymbolCreator: codlsc
LBL1 = THT-14-423-10: Thermal Transfer Printable Labels, 0.650" W x 0.200" H - 10,000 per roll; Manufacturer: Brady; SymbolCreator: a0412235; CompType: Label; Note: Size: 0.65" x 0.20 "
Logo1 = Pb-Free: SymbolCreator: a0412235
LOGO2 = IEC_HighVoltage: IEC 61010-1 High Voltage Warning; SymbolCreator: a0412235
Logo3 = FCC_disclaimer: SymbolCreator: a0412235
Logo4 = CMP-0074769-1
Logo5 = ESD_Susceptible: ESD Susceptible Symbol; SymbolCreator: a0412235
MH1-MH4 = NY PMS 440 0025 PH: Mountin hole, NPTH Drill 3.2mm; CompType: Hardware
ZZ1 = AssemblyNoteLabel: SymbolCreator: a0412235
ZZ2-ZZ4 = AssemblyNote: SymbolCreator: codlsc

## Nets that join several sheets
+3.3V_DVDD: Pg2-Current Sense (16 pins), Pg3-Voltage signal condtioning (9 pins)
+5.0V_PH: Pg3-Voltage signal condtioning (18 pins), Pg6-Power supply 3 (5 pins)
+5.0V_USH: Pg2-Current Sense (C32.1 D25.2 D28.2 J26.2), Pg4-Power supply 1 (5 pins)
+5.0V_VDC: Pg2-Current Sense (C45.1 J31.2), Pg5-Power supply 2 (6 pins)
+5.0V_VSH: Pg2-Current Sense (C33.1 D26.2 D31.2 J27.2), Pg4-Power supply 1 (5 pins)
+5.0V_WSH: Pg2-Current Sense (C34.1 D27.2 D34.2 J22.2), Pg5-Power supply 2 (5 pins)
+5V_CNTL: Pg2-Current Sense (C82.1 C83.1 J32.3 J32.37), Pg4-Power supply 1 (9 pins), Pg5-Power supply 2 (9 pins), Pg6-Power supply 3 (6 pins)
-5.0V_PH: Pg3-Voltage signal condtioning (12 pins), Pg6-Power supply 3 (6 pins)
-5.0V_USH: Pg2-Current Sense (D25.1 D28.1), Pg4-Power supply 1 (6 pins)
-5.0V_VSH: Pg2-Current Sense (D26.1 D31.1), Pg4-Power supply 1 (6 pins)
-5.0V_WSH: Pg2-Current Sense (D27.1 D34.1), Pg5-Power supply 2 (6 pins)
DGND: Pg2-Current Sense (20 pins), Pg3-Voltage signal condtioning (6 pins), Pg4-Power supply 1 (11 pins), Pg5-Power supply 2 (10 pins), Pg6-Power supply 3 (10 pins)
GND_PH: Pg3-Voltage signal condtioning (36 pins), Pg6-Power supply 3 (36 pins)
CLKP_U_PH: Pg2-Current Sense (J32.21), Pg3-Voltage signal condtioning (U8.7)
CLKP_V_PH: Pg2-Current Sense (J32.25), Pg3-Voltage signal condtioning (U9.7)
CLKP_W_PH: Pg2-Current Sense (J32.29), Pg3-Voltage signal condtioning (U10.7)
DOUTP_U_PH: Pg2-Current Sense (J32.19), Pg3-Voltage signal condtioning (R48.2)
DOUTP_V_PH: Pg2-Current Sense (J32.23), Pg3-Voltage signal condtioning (R51.2)
DOUTP_W_PH: Pg2-Current Sense (J32.27), Pg3-Voltage signal condtioning (R55.2)

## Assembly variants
001: not fitted C3 C4 C5 C6 C7 C8 C10 C11 C12 C13 C14 C16 C21 C22 C23 C24 C25 C26 C29 C30 C31 C37 C38 C40 C41 C43 C44 C51 C53 C55 LBL1 R16 R17 R18 R25 R29 R31 R43 R58 U2 U3 U4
